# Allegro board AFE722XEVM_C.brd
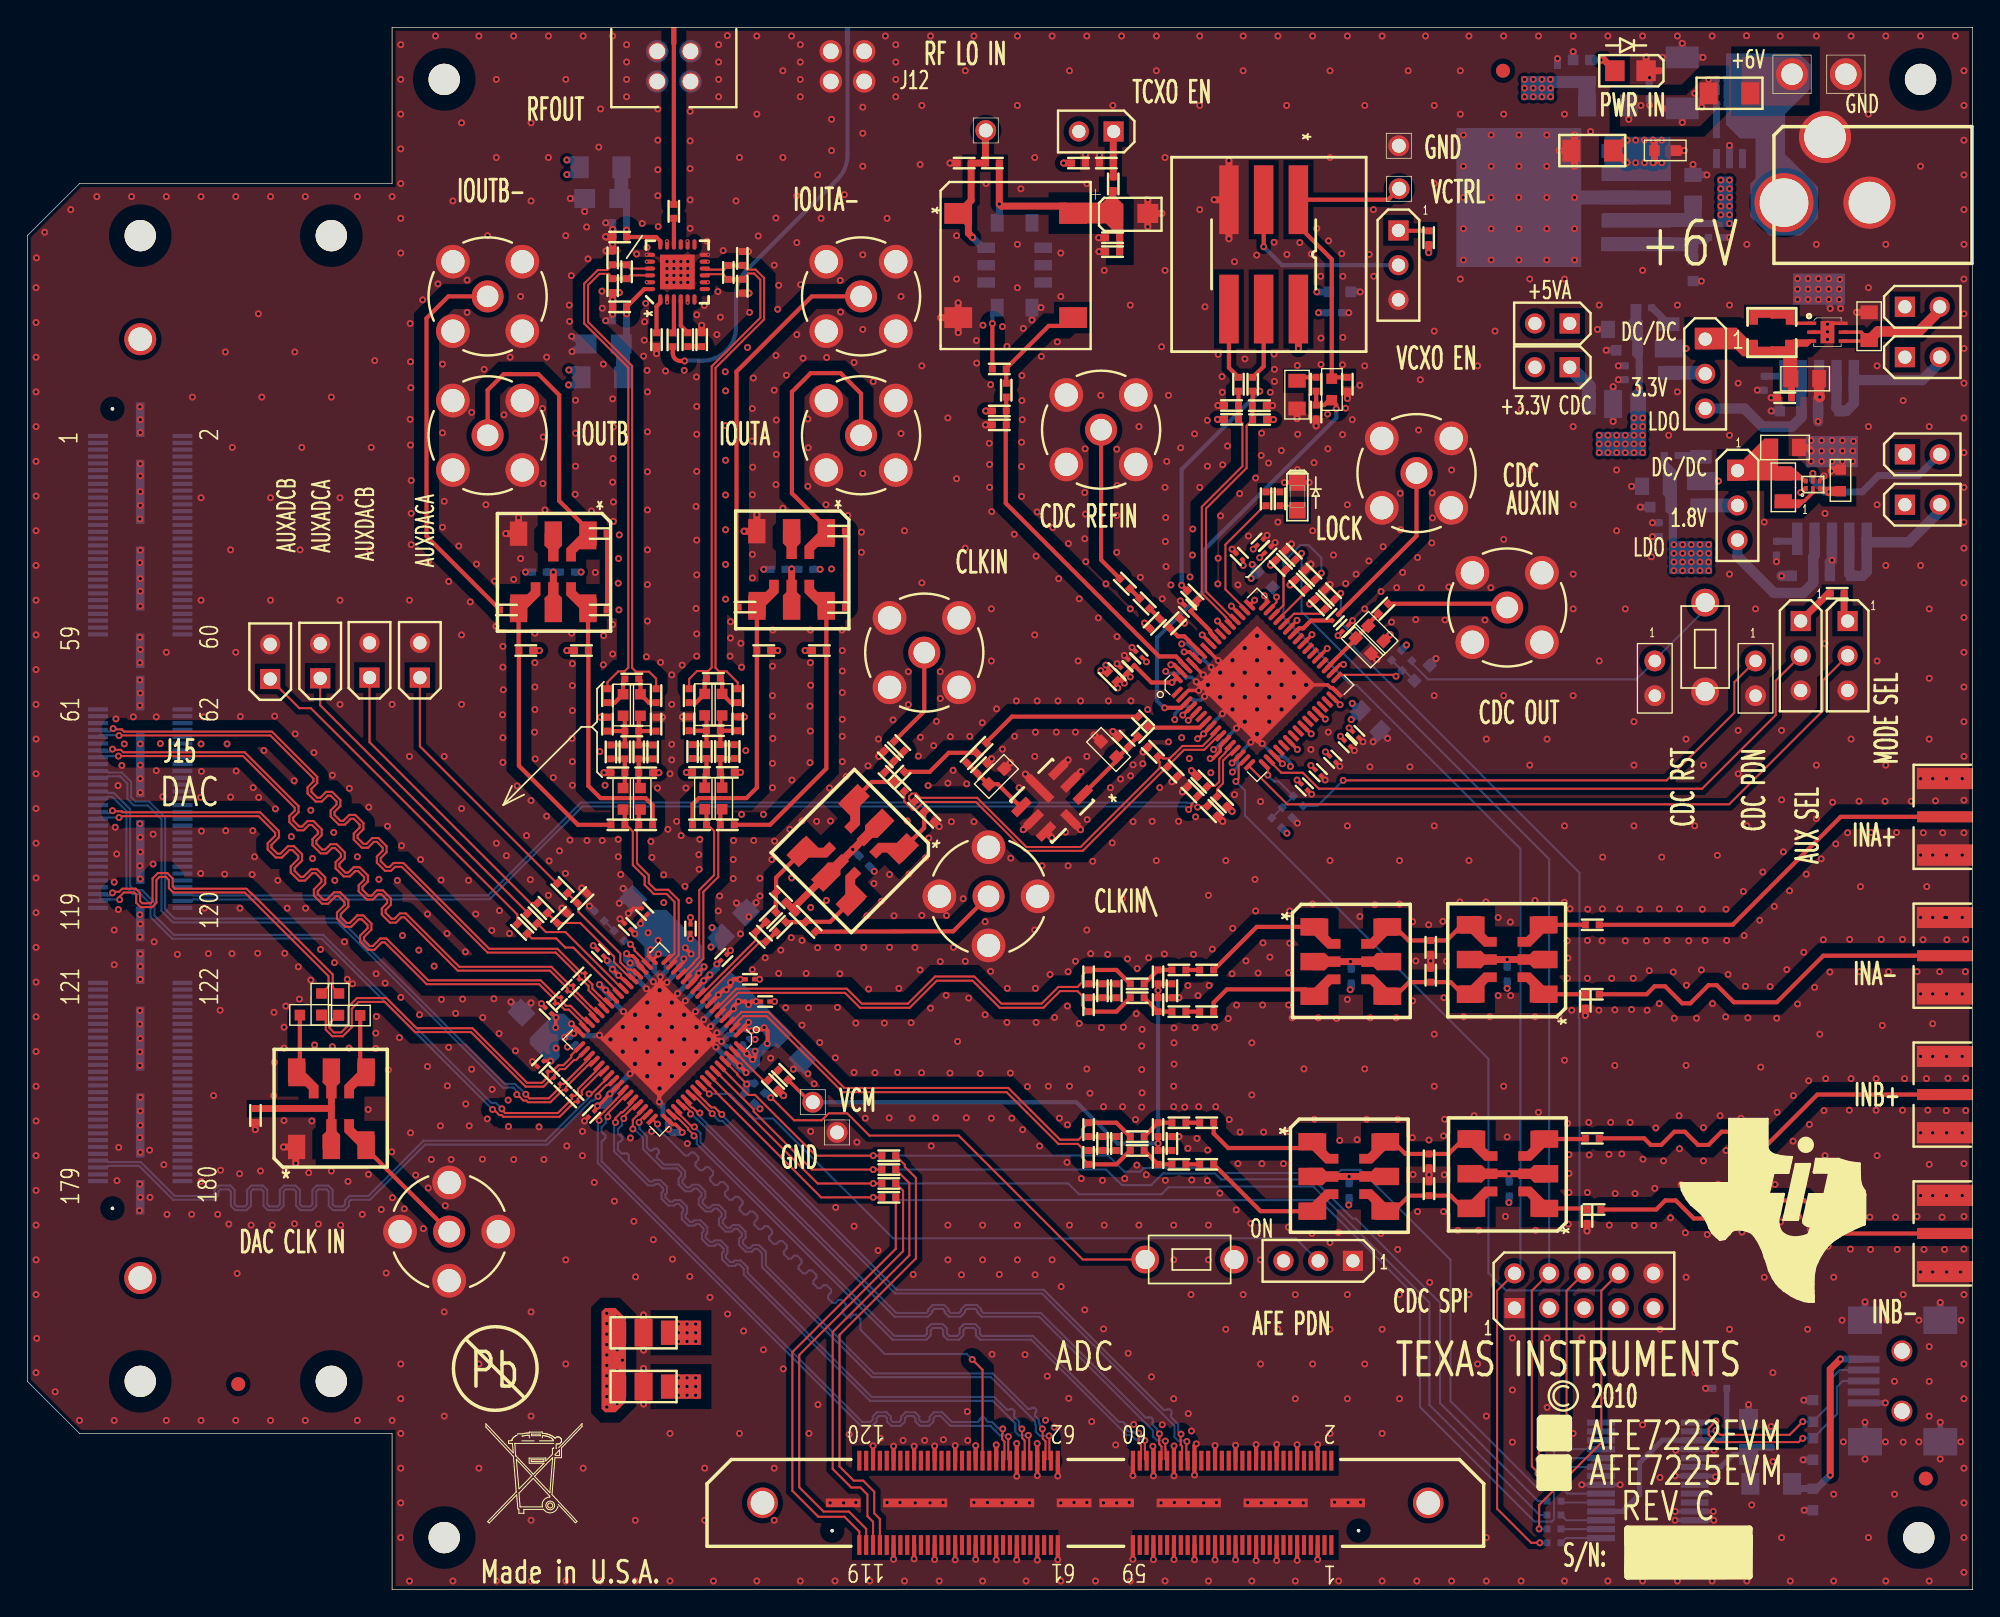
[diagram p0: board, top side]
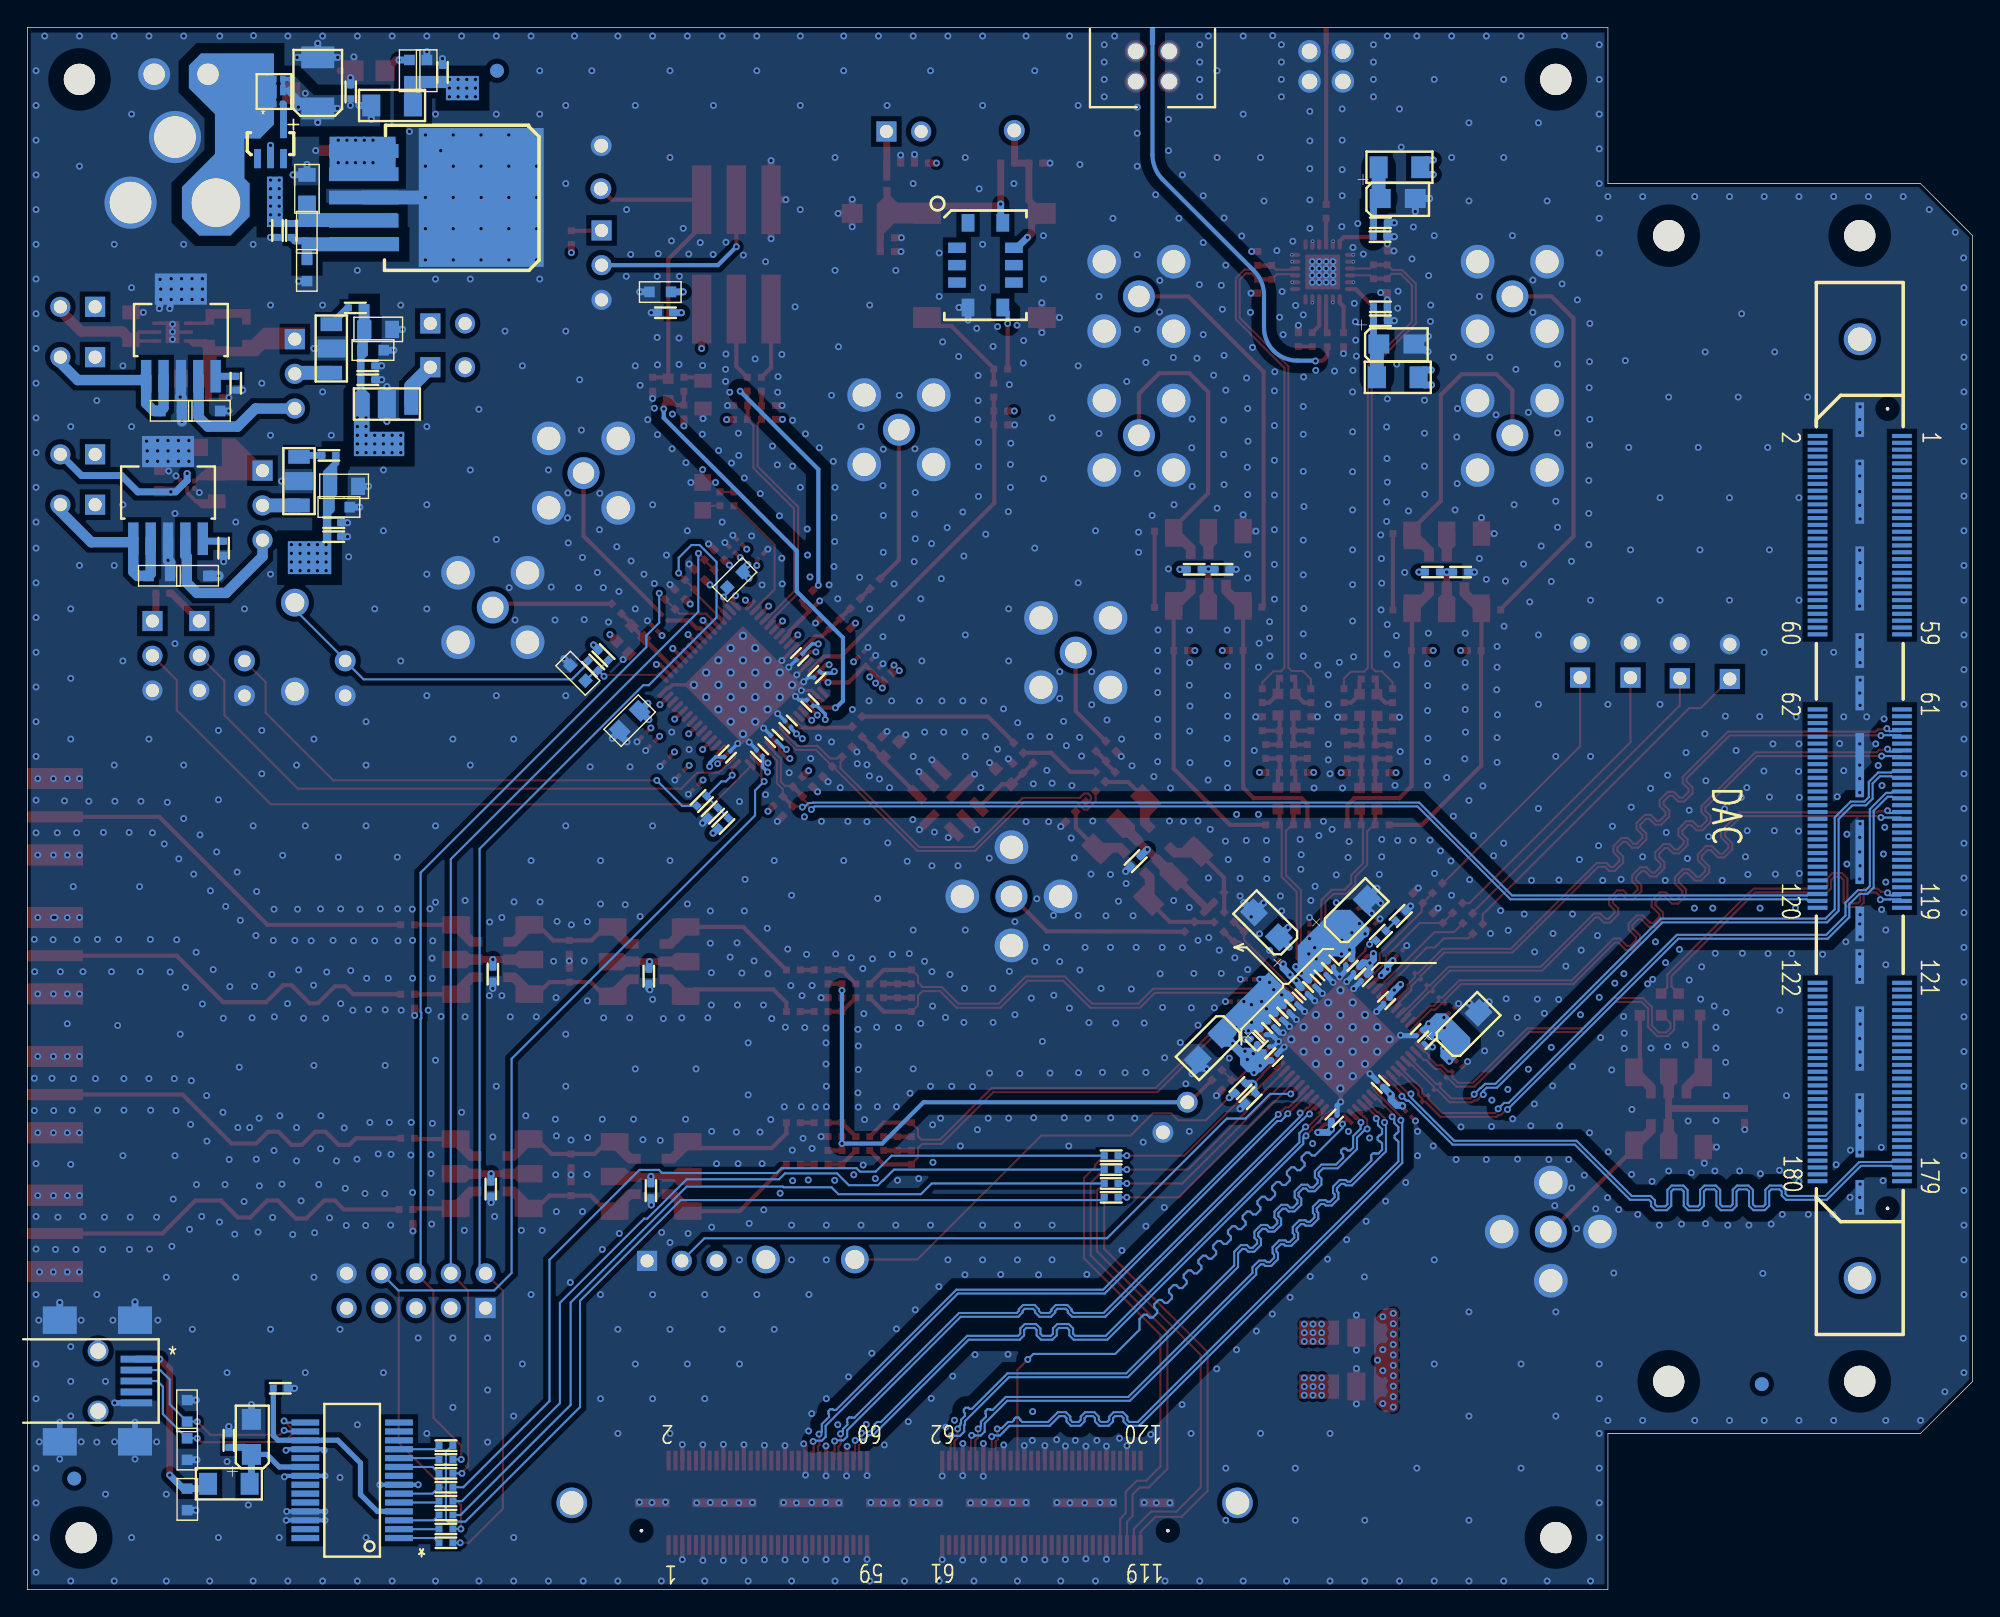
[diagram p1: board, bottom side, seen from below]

Outline 142.24 x 114.3 mm; copper layers: TOP, L2_GND, L3_PWR, L4_PWR, L5_GND, BOTTOM. Coordinates in mm from the lower left corner of the outline.
Outline path: 0,99.06 0,15.24 3.81,11.43 26.67,11.43 26.67,0 142.24,0 142.24,114.3 26.67,114.3 26.67,102.87 3.81,102.87 0,99.06

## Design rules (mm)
net group ADC_DCLKOUT: nets ADC_DCLKOUTN ADC_DCLKOUTP
net group ADC_FCLKOUT: nets ADC_FCLKOUTN ADC_FCLKOUTP
net group ADCA_DATA_0: nets ADCA_DATA_0N ADCA_DATA_0P
net group ADCA_DATA_1: nets ADCA_DATA_1N ADCA_DATA_1P
net group ADCB_DATA_0: nets ADCB_DATA_0N ADCB_DATA_0P
net group ADCB_DATA_1: nets ADCB_DATA_1N ADCB_DATA_1P
net group DAC_DCLK_IN: nets DAC_DCLK_INN DAC_DCLK_INP
net group DAC_FCLK_IN: nets DAC_FCLK_INN DAC_FCLK_INP
net group DACA_DATA_0: nets DACA_DATA_0N DACA_DATA_0P
net group DACA_DATA_1: nets DACA_DATA_1N DACA_DATA_1P
net group DACB_DATA_0: nets DACB_DATA_0N DACB_DATA_0P
net group DACB_DATA_1: nets DACB_DATA_1N DACB_DATA_1P
net group DP1: nets QN1 QP1
net group DP2: nets IN1 IP1
net group DP3: nets N31634141 N31634154
net group FPGA_CLK: nets FPGA_CLKN FPGA_CLKP
net group PWR: nets N29978744 N29978893
net group SYNCIN: nets SYNCINN SYNCINP
net group Y1: nets Y1N Y1P
net group 50 OHM: nets N27753768
net group PWR_PH: nets N27753749

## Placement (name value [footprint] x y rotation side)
C1  .1uF  [0402]  54.61 36.83 315 top
C2  .01uF  [0201]  50.93 46.25 45 top
C3  10uF  [TANT_A]  51.64 48.64 45 bottom
C4  4700pF  [0201]  48.87 43.82 225 bottom
C5  .01uF  [0201]  42.85 43.1 315 bottom
C6  4700pF  [0201]  37.54 38.46 225 top
C7  .01uF  [0201]  40.46 40.74 315 bottom
C8  4700pF  [0201]  38.1 42.37 135 top
C9  .01uF  [0201]  43.31 36.98 45 bottom
C10  4700pF  [0201]  41.25 34.8 225 top
C11  10uF  [TANT_A]  37.03 41.3 135 bottom
C12  .01uF  [0201]  44.5 44.78 315 bottom
C13  4700pF  [0201]  45.06 45.36 315 bottom
C14  .01uF  [0201]  45.14 49.63 135 top
C15  .01uF  [0201]  46.94 45.77 225 bottom
C16  .01uF  [0201]  48.31 44.37 225 bottom
C17  4700pF  [0201]  43.89 48.51 135 top
C18  10uF  [TANT_A]  45.21 49.63 135 bottom
C19  4700pF  [0201]  39.9 40.18 315 bottom
C20  .01uF  [0201]  46.69 34.49 135 bottom
C21  4700pF  [0201]  47.5 45.21 225 bottom
C22  4700pF  [0201]  48.49 48.36 90 top
C23  4700pF  [0201]  52.83 44.65 0 top
C24  4700pF  [0201]  50.75 41.94 225 bottom
C25  4700pF  [0201]  53.95 43.03 0 top
C26  4700pF  [0201]  51.87 40.82 225 bottom
C27  4700pF  [0201]  51.08 38.94 135 bottom
C28  .01uF  [0201]  51.64 39.52 135 bottom
C29  .01uF  [0201]  49.63 43.05 225 bottom
C30  .01uF  [0201]  52.53 40.11 45 bottom
C31  .01uF  [0201]  50.19 42.49 225 bottom
C32  .01uF  [0201]  51.31 41.38 225 bottom
C33  .01uF  [0201]  45.62 45.92 315 bottom
C34  4700pF  [0201]  41.91 46.58 135 top
C35  10uF  [TANT_A]  55.75 39.7 315 bottom
C36  .1uF  [0402]  84.07 34.16 180 top
C37  .1uF  [0402]  83.69 32.51 270 top
C38  3.3pF  [0402]  78.61 32.51 270 top
C39  .1uF  [0402]  108.36 29.44 90 bottom
C40  .1uF  [0402]  96.65 29.31 90 bottom
C41  .1uF  [0402]  84.07 31.11 180 top
C42  .1uF  [0402]  84.07 45.34 180 top
C43  .1uF  [0402]  83.69 43.94 90 top
C44  3.3pF  [0402]  78.61 43.69 270 top
C45  .1uF  [0402]  108.2 45.16 90 bottom
C46  .1uF  [0402]  96.8 45.01 90 bottom
C47  .1uF  [0402]  84.07 42.29 180 top
C48  .1uF  [0402]  96.52 88.32 90 top
C49  .1uF  [0402]  94.23 86.28 90 top
C50  .1uF  [0603]  95.96 94.95 0 bottom
C51  .1uF  [0402]  54.28 49.12 225 top
C52  22uF  [0805]  92.84 87.43 90 top
C53  100pF  [0402]  95.71 93.42 0 bottom
C54  0 ohm  [0402]  89.6 88.06 270 top
C55  .1uF  [0402]  55.02 48.39 225 top
C56  .1uF  [0402]  61.29 53.21 315 bottom
C57  10nF  [0402]  81.79 72.06 315 top
C58  0 ohm  [0402]  88.56 88.06 270 top
C59  .022uF  [0201]  91.06 61.14 135 bottom
C60  .1uF  [0402]  16.68 34.82 90 top
C61  .022uF  [0201]  80.72 67.84 315 top
C62  100pF  [0201]  97.13 62.56 315 top
C63  .022uF  [0201]  88.62 75.59 135 top
C64  .022uF  [0201]  85.78 68.25 315 bottom
C65  100pF  [0201]  80.16 67.26 315 top
C66  100pF  [0201]  90.14 76.63 45 top
C67  100pF  [0201]  81.28 68.43 135 top
C68  .022uF  [0201]  90.7 76.07 45 top
C69  100pF  [0201]  96.37 70.33 45 top
C70  22pF  [0402]  68.96 60.76 225 top
C71  22pF  [0402]  81.66 62.87 45 top
C72  1pF  [0402]  80.24 61.93 315 top
C73  1pF  [0402]  69.72 59.99 225 top
C74  .1uF  [0402]  99.06 71.68 225 top
C75  1uF  [0603]  101.98 67.06 45 bottom
C76  10nF  [0201]  84.51 66.95 315 bottom
C77  4.7uF  [0805]  98.2 63.58 315 bottom
C78  10nF  [0201]  85.01 64.87 45 bottom
C79  .1uF  [0402]  54.76 74.65 180 bottom
C80  10nF  [0201]  88.7 61.21 45 bottom
C81  .1uF  [0402]  37.31 74.45 180 bottom
C82  10nF  [0201]  87.66 62.28 45 bottom
C83  10nF  [0201]  95.63 71.12 45 top
C84  10nF  [0201]  86.61 63.32 45 bottom
C85  10nF  [0201]  84.84 71.81 315 top
C86  10nF  [0201]  93.37 58.72 315 top
C88  10nF  [0201]  96.52 61.9 315 top
C89  10nF  [0402]  92.2 56.77 315 bottom
C90  .01uF  [0402]  43.69 61.42 90 top
C91  4.7pF  [0402]  44.32 62.81 0 top
C92  4.7pF  [0402]  44.32 66.62 0 top
C94  .01uF  [0402]  44.7 61.42 90 top
C95  4.7pF  [0402]  42.8 95.53 90 top
C96  4.7pF  [0402]  42.8 97.31 270 top
C97  4.7uF  [TANT_A]  42.14 91.14 180 bottom
C98  1000pF  [0402]  43.18 93.85 180 bottom
C99  .1uF  [0402]  43.18 92.84 180 bottom
C100  3.3pF  [0402]  43.18 93.85 180 top
C101  3.3pF  [0402]  43.18 98.96 180 top
C102  1000pF  [0402]  43.21 98.98 180 bottom
C103  22pF  [0402]  47.19 91.57 90 top
C104  .1uF  [0402]  43.18 100 180 bottom
C105  4.7uF  [TANT_A]  42.04 101.78 180 bottom
C106  22pF  [0402]  47.27 100.97 90 top
C107  22pF  [0402]  48.29 91.32 270 top
C108  4.7pF  [0402]  52.28 95.49 90 top
C109  4.7pF  [0402]  52.28 97.27 270 top
C110  .01uF  [0402]  51.69 61.44 90 top
C111  4.7pF  [0402]  50.04 62.84 180 top
C112  4.7pF  [0402]  50.04 66.67 180 top
C114  .01uF  [0402]  48.64 61.44 90 top
C115  .1uF  [0402]  127.51 11.05 90 bottom
C116  10nF  [0603]  130.56 6.6 270 bottom
C117  4.7uF  [TANT_A]  125.86 11.18 90 bottom
C118  47pF  [0603]  130.56 10.29 270 bottom
C119  47pF  [0603]  130.56 13.08 90 bottom
C120  .1uF  [0402]  123.62 14.73 180 bottom
C121  47uF  [TANT_B]  121.01 110.24 90 bottom
C122  .1uF  [0402]  118.59 109.7 90 bottom
C123  1uF  [0603]  113.03 111.12 90 bottom
C124  .01uF  [0402]  111.89 111.12 90 bottom
C125  10uF  [1206]  114.43 105.28 180 top
C128  .1uF  [0402]  123.95 99.31 270 bottom
C130  10uF  [0805]  134.67 92.43 90 top
C131  10uF  [0805]  116.59 92.2 180 bottom
C132  10nF  [0402]  128.37 87.2 180 top
C133  10uF  [0805]  130 88.6 0 top
C135  10nF  [0402]  127 88.14 270 bottom
C136  1uF  [0603]  128.93 86.23 180 bottom
C137  2.2uF  [0603]  132.59 81.15 90 top
C138  4.7uF  [0805]  128.52 83.57 0 top
C139  .1uF  [0402]  119.71 78.05 180 bottom
C140  1uF  [0603]  132.59 74.17 180 bottom
C141  .01uF  [0402]  127.89 76.07 270 bottom
C142  4.7uF  [0603]  129.79 74.17 180 bottom
C143  1uF  [0603]  116.97 90.68 180 bottom
C144  10nF  [0201]  95.45 60.76 315 top
C145  .1uF  [0402]  117.22 89.53 180 bottom
C146  10nF  [0201]  94.39 59.77 315 top
C147  10nF  [0402]  117.22 88.52 180 bottom
C148  10uF  [0805]  119.08 80.72 180 bottom
C149  1uF  [0603]  119.46 79.2 180 bottom
C150  10nF  [0402]  119.71 77.04 180 bottom
C151  2.2uF  [0603]  131.72 86.23 180 bottom
C177  .1uF  [0402]  71.58 87.63 270 top
C178  100pF  [0402]  79.22 97.89 180 top
C179  4.7uF  [0402]  76.99 104.37 0 top
C180  .1uF  [0402]  78.77 104.37 180 top
C181  10uF  [TANT_A]  80.64 100.69 0 top
C182  .1uF  [0402]  79.22 98.91 180 top
C186  1uF  [0603]  119.76 105.28 0 top
C187  10uF  [0805]  121.79 102.49 90 bottom
C414  15pF  [0402]  122.94 99.31 270 bottom
D1  GREEN  [SMD_LED_0805]  92.86 79.98 90 top
D2  Blue  [LED_0805]  117.22 111.12 0 top
F3  2 AMP 63V FAST SMD  [1206]  124.46 109.47 180 top
FB4  68 ohm @ 100MHz  [1206]  42.04 88.7 0 bottom
FB5  68 ohm @ 100MHz  [1206]  41.91 104.06 0 bottom
FB6  68 OHM @ 100MHz  [1206]  127.51 7.75 0 bottom
FB7  68 ohm @ 100MHz  [1206]  115.57 108.59 0 bottom
FB9  27uF  [1206_BEAD_NFM31P]  120.02 90.81 90 bottom
FB11  27uF  [1206_BEAD_NFM31P]  45.06 14.86 180 top
FB12  27uF  [1206_BEAD_NFM31P]  122.38 81.1 90 bottom
FB13  1K  [IND_0402]  79.32 66.8 135 top
FB15  27uF  [1206_BEAD_NFM31P]  115.95 86.74 180 bottom
FB17  27uF  [1206_BEAD_NFM31P]  45.06 18.8 180 top
FB25  1K  [0402]  79.4 102.97 90 top
FLT1  245.76MHz  [FILTER_8_SM_150X150]  74.93 57.71 225 top
J1  SMA_END_JACK_RND  [SMA_SMEL_250X215]  142.24 36.22 270 top
J2  SMA_END_JACK_RND  [SMA_SMEL_250X215]  142.24 26.06 270 top
J3  SMA_END_JACK_RND  [SMA_SMEL_250X215]  142.24 56.54 270 top
J4  SMA_END_JACK_RND  [SMA_SMEL_250X215]  142.24 46.38 270 top
J5  SMA_PCB_THVT  [SMA_THVT_312X312]  60.96 84.45 0 top
J6  SMA_PCB_THVT  [SMA_THVT_312X312]  60.96 94.62 0 top
J7  SMA_PCB_THVT  [SMA_THVT_312X312]  33.66 84.45 0 top
J8  SMA_PCB_THVT  [SMA_THVT_312X312]  33.66 94.62 0 top
J9  SMA_PCB_THVT  [SMA_THVT_312X312]  78.51 84.86 270 top
J10  SMA_PCB_THVT  [SMA_THVT_312X312]  101.57 81.69 90 top
J11  SMA_PCB_THVT  [SMA_THVT_312X312]  108.2 71.86 270 top
J12  SMA_END_JACK_RND  [SMA_SMEL_218X247_096]  59.97 114.3 180 bottom
J13  SMA_END_JACK_RND  [SMA_SMEL_218X247_096]  47.27 114.3 0 top
J14  QTH-060-01-F-D-A-RT1  [CON_SMVT_120POS_QTH_SAMTEC_RT1]  78.11 6.35 180 top
J15  CON, SMVT, 180POS, HS GND PLANE, QTH  [CON_SMVT_180POS_QTH_SAMTEC_RT1]  6.22 86.36 270 bottom
J16  USB_MINI_AB  [CON_SMRT_USBMNE20_F]  137.72 15.27 180 bottom
J17  CONN JACK PWR  [CON_RAPC722_JACK_THVT_3]  131.57 101.47 90 top
J18  SMA_PCB_THVT  [SMA_THVT_312X312]  65.58 68.55 90 top
J19  SMA_PCB_THVT  [SMA_THVT_312X312]  70.28 50.72 225 top
J20  HMTSW-105-07-G-D-.240  [HDR_THVT_2X5_100_M]  108.74 20.6 90 top
J21  SMA_PCB_THVT  [SMA_THVT_312X312]  30.84 26.19 135 top
JP1  HEADER_1x3_100_430L  [HDR_THVT_1X3_100_M]  96.93 24.05 270 top
JP2  HEADER_1x2_100_430L  [HDR_THVT_1X2_100_M]  28.7 66.73 180 top
JP3  HEADER_1x2_100_430L  [HDR_THVT_1X2_100_M]  25.02 66.73 180 top
JP4  HEADER 3POS  [HDR_THVT_1X3_100_M]  100.25 99.44 0 top
JP5  HEADER 3POS  [HDR_THVT_1X3_100_M]  133.1 70.87 0 top
JP6  HEADER 2POS  [JUMPER2]  119 67.95 270 top
JP7  HEADER 3POS  [HDR_THVT_1X3_100_M]  129.67 70.87 0 top
JP8  HEADER 2POS  [JUMPER2]  126.37 67.95 270 top
JP10  HEADER_1x2_100_430L  [HDR_THVT_1X2_100_M]  112.78 92.63 270 top
JP11  HEADER_1x2_100_430L  [HDR_THVT_1X2_100_M]  137.29 93.85 90 top
JP12  HEADER 3POS  [HDR_THVT_1X3_100_M]  122.68 91.49 0 top
JP13  JUMPER_1x3_100_430L  [HDR_THVT_1X3_100_M]  125.04 81.86 0 top
JP14  HEADER_1x2_100_430L  [HDR_THVT_1X2_100_M]  137.29 79.38 90 top
JP15  HEADER_1x2_100_430L  [HDR_THVT_1X2_100_M]  21.41 66.67 180 top
JP16  HEADER_1x2_100_430L  [HDR_THVT_1X2_100_M]  17.75 66.62 180 top
JP17  HEADER_1x2_100_430L  [HDR_THVT_1X2_100_M]  79.43 106.68 270 top
JP18  HEADER_1x2_100_430L  [HDR_THVT_1X2_100_M]  112.78 89.43 270 top
JP19  HEADER_1x2_100_430L  [HDR_THVT_1X2_100_M]  137.29 90.17 90 top
JP20  HEADER_1x2_100_430L  [HDR_THVT_1X2_100_M]  137.29 83.06 90 top
L1  72nH  [0402]  79.63 32.51 270 top
L2  72nH  [0402]  79.63 43.69 270 top
L8  180nH  [0603]  70.87 59.49 45 top
L9  180nH  [0603]  79.07 61.48 135 top
L10  180nH  [0603]  43.56 64.72 270 top
L12  180nH  [0603]  44.83 64.72 270 top
L14  180nH  [0603]  50.8 64.74 270 top
L16  180nH  [0603]  49.53 64.74 270 top
L18  2.2uH  [LPS3015]  127.56 91.97 270 top
L19  2.2uH  [0805]  128.4 80.64 90 top
NOREF  -  []  0 15.24 90 top
NOREF#2  -  [unnamed#2]  30.48 3.81 0 top
NOREF#3  -  [unnamed#2]  8.25 15.24 0 top
NOREF#4  -  []  26.67 102.87 90 top
NOREF#5  -  []  -18.92 115.57 0 top
NOREF#6  -  []  40.51 52.96 0 top
NOREF#7  -  [unnamed#2]  138.3 3.81 0 top
NOREF#8  -  []  110.06 11.53 0 top
NOREF#9  -  []  36.98 8.66 0 top
NOREF#10  -  []  142.24 0 90 top
NOREF#11  -  []  -12.24 58.65 0 top
NOREF#12  -  []  26.67 114.3 0 top
NOREF#13  -  [unnamed#2]  22.23 99.06 0 top
NOREF#14  -  [unnamed#2]  30.48 110.49 0 top
NOREF#15  -  []  698.75 109.09 0 top
NOREF#16  -  []  -130.81 -80.01 0 top
NOREF#17  -  []  -123.19 -184.15 0 top
NOREF#18  -  [unnamed#2]  138.43 110.49 0 top
NOREF#19  -  [unnamed#3]  138.81 8.13 0 top
NOREF#20  -  [unnamed#3]  107.9 111.12 0 top
NOREF#21  -  []  32.99 0.56 0 top
NOREF#22  -  [unnamed#2]  8.25 99.06 0 top
NOREF#23  -  [unnamed#2]  22.23 15.24 0 top
NOREF#24  -  []  68.29 52.49 0 top
NOREF#25  -  [unnamed#3]  15.42 15.04 0 top
NOREF#26  -  [unnamed#3]  138.81 8.13 180 bottom
NOREF#27  -  [unnamed#3]  107.9 111.12 180 bottom
NOREF#28  -  [unnamed#3]  15.42 15.04 180 bottom
Q1  CSD17313Q2  [MOSFET_8_2MMX2MM_0P65]  124.21 109.6 180 bottom
R1  0 ohm  [0402]  63.12 30.73 0 bottom
R2  10  [0402]  53.44 36.78 135 bottom
R3  0 ohm  [0402]  63.12 30.73 0 top
R5  10K  [0402]  52.88 35.86 315 bottom
R6  0 ohm  [0402]  63.12 29.72 0 bottom
R7  10  [0402]  55.17 37.74 135 top
R8  0 ohm  [0402]  63.12 29.72 0 top
R9  0 ohm  [0402]  63.12 28.7 0 bottom
R10  0 ohm  [0402]  63.12 28.7 0 top
R11  0 ohm  [0402]  63.12 31.75 0 bottom
R12  100  [0402]  58.04 68.71 0 top
R13  100  [0402]  53.72 68.71 180 top
R14  6.98  [0402]  41.91 49.2 315 bottom
R15  953  [0402]  43.36 47.75 315 bottom
R16  0  [0402]  39.04 51.41 135 top
R17  0  [0402]  37.57 49.96 135 top
R18  0  [0402]  36.83 49.2 135 top
R19  0  [0402]  36.09 48.44 135 top
R20  0  [0402]  86.36 34.16 0 top
R21  10  [0402]  81.03 33.15 180 top
R22  0  [0402]  114.3 33.02 180 top
R23  10  [0402]  77.6 33.53 270 top
R24  49.9  [0402]  102.49 31.24 270 top
R25  24.9  [0402]  82.68 33.53 270 top
R26  49.9  [0402]  102.49 29.21 270 top
R27  24.9  [0402]  82.68 31.5 270 top
R28  10  [0402]  77.6 31.5 270 top
R29  0  [0402]  114.68 27.81 0 top
R30  0  [0402]  86.36 31.11 0 top
R31  0  [0402]  114.05 27.18 270 top
R32  10  [0402]  81.03 32.13 180 top
R33  0  [0402]  86.36 45.34 0 top
R34  10  [0402]  81.03 44.32 180 top
R35  10  [0402]  77.6 44.7 270 top
R36  0  [0402]  114.3 48.64 180 top
R37  49.9  [0402]  102.62 46.86 270 top
R38  24.9  [0402]  82.68 44.7 270 top
R39  49.9  [0402]  102.62 44.83 270 top
R40  24.9  [0402]  82.68 42.67 270 top
R41  10  [0402]  77.6 42.67 270 top
R42  0  [0402]  114.55 43.56 0 top
R43  0  [0402]  86.36 42.29 0 top
R44  10  [0402]  81.03 43.31 180 top
R45  0  [0402]  113.92 42.93 270 top
R46  0  [0402]  51.05 55.96 180 top
R47  0  [0402]  59.44 71.86 0 top
R48  0  [0402]  57.05 74.65 0 bottom
R49  0  [0402]  59.18 77.44 180 top
R50  0  [0402]  39.62 74.45 0 bottom
R51  0 ohm  [0402]  63.12 31.75 0 top
R52  49.9  [0402]  40.67 50.67 45 top
R53  100  [0402]  40.64 68.71 0 top
R54  100  [0402]  36.32 68.71 180 top
R55  100  [0201]  40.03 35.92 315 top
R56  0  [0402]  49.28 55.96 0 top
R57  0  [0402]  52.35 71.88 180 top
R58  0  [0402]  45.09 55.96 180 top
R59  0  [0402]  42.01 71.68 0 top
R60  100  [0201]  39.17 36.78 315 top
R61  0  [0402]  41.76 77.27 180 top
R62  100  [0201]  38.28 37.67 315 top
R63  49.9  [0402]  39.19 49.23 45 top
R64  0  [0603]  22.78 42.83 90 top
R65  100  [0201]  38.81 43.1 225 top
R66  100  [0201]  39.7 43.99 225 top
R67  100  [0201]  40.56 44.88 225 top
R68  0  [0402]  43.31 55.96 0 top
R69  0  [0402]  34.9 71.68 180 top
R70  1K  [0603]  95.38 87.81 270 top
R71  7.15K  [0402]  94.23 88.06 270 top
R72  0 ohm  [0402]  81.66 63.42 315 top
R73  10K  [0402]  102.46 98.78 270 top
R74  0 ohm  [0402]  62.97 59.54 135 top
R75  0 ohm  [0402]  80.16 73.69 135 top
R76  0 ohm  [0402]  63.86 59.56 45 top
R77  49.9  [0402]  62.92 61.06 135 top
R78  100  [0402]  55.19 50.57 315 top
R79  0 ohm  [0402]  63.86 58.67 315 top
R80  130  [0402]  90.23 85.6 0 top
R81  0 ohm  [0402]  65.13 57.38 135 top
R82  100  [0402]  56.64 49.12 315 top
R83  82.5  [0402]  90.21 86.63 0 top
R84  49.9  [0402]  85.09 72.82 135 top
R85  10K  [0402]  82.35 70.59 225 top
R86  0 ohm  [0402]  66.04 56.46 315 top
R87  130  [0402]  87.92 85.62 180 top
R88  100  [0402]  53.72 47.68 315 top
R89  82.5  [0402]  87.92 86.63 180 top
R90  10K  [0402]  83.81 70.61 225 top
R91  0 ohm  [0402]  90.58 79.68 270 top
R92  750  [0402]  91.59 79.93 90 top
R93  0  [0603]  21.51 42.83 90 top
R94  0  [0603]  23.55 42.02 180 top
R95  0  [0603]  20.71 42.04 0 top
R96  150  [0402]  82.21 61.39 135 top
R97  150  [0402]  83.83 59.77 315 top
R98  10K  [0402]  94.44 72.18 135 top
R99  10K  [0402]  93 73.62 135 top
R100  10K  [0402]  91.56 75.06 135 top
R101  10K  [0603]  90.5 73.89 135 bottom
R102  10K  [0402]  95.33 72.72 315 top
R103  10K  [0402]  93.9 74.16 315 top
R104  10K  [0402]  92.46 75.62 315 top
R105  ??  [0603]  98.6 69.95 315 top
R106  10K  [0402]  100.2 68.45 45 bottom
R107  10K  [0402]  132.21 72.9 180 top
R108  ??  [0603]  97.68 69.06 135 top
R109  100  [0402]  100.97 67.69 45 bottom
R110  10K  [0402]  91.44 56.01 315 bottom
R111  100  [0402]  92.84 57.79 135 bottom
R112  0 ohm  [0402]  63.65 61.8 135 top
R113  115  [0402]  43.31 59.77 0 top
R114  0  [0603]  43.56 57.86 270 top
R115  0  [0402]  42.67 61.42 90 top
R116  634  [0402]  42.42 63.45 90 top
R117  37.4  [0402]  42.42 65.28 270 top
R118  115  [0402]  45.09 59.77 180 top
R119  1.5K  [0603]  121.79 96.52 90 bottom
R120  0  [0603]  44.83 57.86 270 top
R121  0  [0402]  45.72 61.42 90 top
R122  634  [0402]  45.97 63.45 90 top
R123  0  [0402]  46 91.58 90 top
R124  49.9  [0402]  49.31 91.58 90 top
R125  37.4  [0402]  45.97 65.28 270 top
R126  115  [0402]  51.05 59.79 180 top
R127  0  [0603]  50.8 57.89 270 top
R128  0  [0402]  50.67 61.44 90 top
R129  634  [0402]  51.94 63.47 90 top
R130  37.4  [0402]  51.94 65.28 270 top
R131  4.7K  [0603]  121.79 99.31 90 bottom
R132  115  [0402]  49.28 59.79 0 top
R133  0  [0603]  49.53 57.89 270 top
R134  0  [0402]  49.66 61.44 90 top
R135  634  [0402]  48.39 63.47 90 top
R136  0  [0402]  111.76 3.43 0 bottom
R137  0  [0402]  111.76 6.48 0 bottom
R138  0  [0402]  111.76 5.46 0 bottom
R139  0  [0402]  111.76 10.54 0 bottom
R140  37.4  [0402]  48.39 65.28 270 top
R141  0  [0402]  111.76 7.49 0 bottom
R142  10K  [0603]  114.3 111.12 270 bottom
R143  0  [0402]  118.14 93.78 180 bottom
R144  0 ohm  [0402]  69.67 61.49 225 top
R145  0  [0402]  120.07 82.98 180 bottom
R148  130  [0402]  87.27 57.77 135 top
R149  130  [0402]  86.01 59.03 315 top
R150  82.5  [0402]  86.73 56.87 315 top
R151  82.5  [0402]  85.11 58.49 135 top
R154  130  [0402]  51.26 96.24 270 top
R155  130  [0402]  43.81 96.29 270 top
R157  0  [0402]  70.94 89.31 180 top
R158  0  [0402]  111.76 4.45 0 bottom
R159  0  [0402]  111.76 8.51 0 bottom
R160  0  [0402]  111.76 9.53 0 bottom
R161  0 ohm  [0402]  57.18 48.59 135 top
R164  10K  [0402]  68.63 104.37 0 top
R165  10K  [0402]  70.69 104.37 0 top
R166  10K  [0402]  71.2 86.23 0 top
R167  10K  [0402]  71.2 85.22 0 top
SW1  SW PUSHBUTTON  [SW_RESET_PTS635]  84.99 24.16 0 top
SW2  RESET  [SW_RESET_PTS635]  122.68 68.96 270 top
T1  ADTT1-1+  [TFMR_6_RF_DUAL_FOOTPRINT]  108.25 30.43 90 top
T2  ADTT1-1+  [TFMR_6_RF_DUAL_FOOTPRINT]  96.63 30.23 270 top
T3  ADTT1-1+  [TFMR_6_RF_DUAL_FOOTPRINT]  108.2 46.1 90 top
T4  ADTT1-1+  [TFMR_6_RF_DUAL_FOOTPRINT]  96.77 45.95 270 top
T5  ADT4-1WT  [TFMR_6_RF_DUAL_FOOTPRINT]  55.88 74.64 180 top
T6  ADTT1-1+  [TFMR_6_RF_DUAL_FOOTPRINT]  22.23 35.18 0 top
T7  ADT4-1WT  [TFMR_6_RF_DUAL_FOOTPRINT]  38.46 74.47 180 top
T9  ADT4-1WT  [TFMR_6_RF_DUAL_FOOTPRINT]  60.35 54.1 135 top
TP1  Test Point White  [TESTPOINT]  57.43 35.66 0 top
TP2  Test Point Black  [TESTPOINT]  59.21 33.45 0 top
TP3  Test Point Black  [TESTPOINT]  100.28 105.64 0 top
TP4  Test Point White  [TESTPOINT]  100.3 102.49 0 top
TP11  Testloop_Red  [TESTPOINT_62DIA]  129.03 110.87 0 top
TP12  Testloop_Black  [TESTPOINT_62DIA]  132.97 110.87 0 top
TP14  Testloop_White  [TESTPOINT]  70.08 106.76 0 top
U1  AFE7222 or AFE7225  [QFN64]  46.23 40.26 225 top
U2  CDCE72010  [QFN64]  89.91 66.2 45 top
U3  TRF370333  [QFN_24_163X163_0P50MM_PWRPAD]  47.53 96.4 90 top
U4  FT245RL  [SSOP_28_413X221_26]  118.49 8 0 bottom
U6  TPS62291  [SON_DRV_6]  131.62 92 0 top
U7  TPS79633  [SOT_223_6_TG]  130.38 92.15 180 bottom
U8  TPS62231  [SON_DRY_6]  130.56 80.9 0 top
U9  TPS79518  [SOT_223_6_TG]  131.32 80.26 180 bottom
U14  TPS7A4501KTT  [TO_263_6]  110.46 101.85 270 bottom
U16  TCXO 19.2MHz  [SMD_XTAL_7X5MM_D75ASERIES]  72.19 96.9 180 bottom
U17  TCXO 19.2MHz  [OSC_4_SM_460X386]  72.26 96.88 270 top
U18  TPS2400  [DBV5]  124.46 105.79 90 bottom
VCXO1  737.28MHZ  [VCXO_6_CUSTOM2]  90.4 97.69 270 top

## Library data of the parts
C1 C36 C37 C39-C43 C45-C50 C57 C60 C61 C89 C122 C125 C128 C139 C145 = CAP NP: tolerance: 10%
C2 C20 = CAP0402: tolerance: -20%/+80%
C3 C11 C18 C35 = CAP POL-B_10uF_10V
C4 C6 C13 C19 C21 C23-C27 C34 C75 C123 C136 C143 C149 C179 C186 = CAP NP_0: tolerance: 20%
C5 C7 C9 C12 C14-C16 C28-C33 = CAP NP_0: tolerance: -20%/+80%
C8 C10 C17 C22 = CAP0402: tolerance: 20%
C38 C44 = CAP0603: tolerance: +/-.25pF
C51 C55 = CAP0402: tolerance: 10%
C52 = CAP NP: tolerance: 20%
C53 C54 C58 C65 = CAP NP: tolerance: 5%
C56 = CAP0603: tolerance: 10%
C59 C63 C64 C68 C74 C77 C79 C81 C90 C94 C98 C99 C102 C104 C110 C114 C115 C120 C124 C177 C178 C180 C182 = CAP NP_0: tolerance: 10%
C62 C66 C67 C69 C95 C96 C103 C106-C109 C414 = CAP NP_0: tolerance: 5%
C70 C71 = CAP NP: tolerance: 2%
C72 C73 = CAP NP: tolerance: .25pF
C76 C78 C80 C82-C86 C88 C144 C146 = CAP NP: tolerance: 10V
C91 C92 C111 C112 = CAP NP_0: tolerance: .25pF
C97 C105 C117 = CAP POL-B_10uF_10V: tolerance: 10%
C100 C101 = CAP0402
C116 C118 C119 = CAP0603
C121 = CAP POL: tolerance: 20%
C130 C133 C137 C138 C141 C142 C151 C187 = CAP0201: tolerance: 10%
C131 C140 C148 = CAP0201: tolerance: 20%
C132 C135 C147 C150 = CAPACITOR_NP_4: tolerance: 10%
C181 = CAP POL-B_10uF_10V: tolerance: 20%
D1 D2 = LED
F3 = FUSE/SM
FB4-FB7 FB25 = FERRITE_BEAD
FB9 FB11 FB12 FB15 FB17 = BEAD_NFM31P
FB13 = FERRITE_BEAD_0402_H
FLT1 = TS-38S_0
J1-J4 J9-J11 J18 J19 = SMA-END_JACK_142-0711-821_ROUND
J5-J8 J21 = SMA_PCB_THVT_142-0701-201_REC
J12 J13 = SMA-END_JACK_142-0761-801_ROUND
J14 = CON_SMVT_120POS_QTH_SAMTEC
J15 = CON_SMVT_180POS_QTH_SAMTEC
J16 = USB_MINI_AB_MNE20-5G5P10
J17 = CONN JACK PWR
J20 = HEADER_2x5_100
JP1 JP12 = JUMPER_1x3_100
JP2 JP3 JP10 JP11 JP14-JP20 = JUMPER_1x2_100
JP4 = HEADER_1x3_0
JP5 JP7 = Jumper_1x3_smt
JP6 JP8 = HEADER_1x2_0: User Part Number: ***
JP13 = Jumper_1x3_100_1
L1 L2 = CHOKE_0
L8 L9 = INDUCTOR: tolerance: 5%
L10 L12 L14 L16 = IND0603_0: tolerance: 2%
L18 = IND1206
L19 = IND1206: tolerance: 20%
Q1 = PWR_MOSFET_CSD17313Q2
R1 R3 R6 R8-R11 R16-R20 R22 R29-R31 R33 R36 R42 R43 R45-R51 R56-R59 R61 R64 R68 R69 R72 R74-R76 R79 R81 R86 R91 R93-R95 R112 R114 R120 R123 R127 R133 R136-R139 R141 R143-R145 R157-R161 = R: tolerance: 5%
R2 R5 R12 R13 R53 R54 R71 R73 R85 R90 R98-R108 R110 R117 R124 R125 R130 R140 R164-R167 = R: tolerance: 1%
R7 R21 R23-R28 R32 R34 R35 R37-R41 R44 R52 R55 R60 R62 R63 R65-R67 R77 R78 R82 R88 R142 R154 R155 = RES0603: tolerance: 1%
R14 R15 = R_0: tolerance: 1%
R70 = RES0603
R80 R83 R87 R89 R92 R96 R97 R109 R111 R148-R151 = RESISTOR: tolerance: 1%
R84 = RES0402: tolerance: 1%
R113 R116 R118 R122 R126 R129 R132 R135 = R_5: tolerance: 1%
R115 R121 R128 R134 = R_5: tolerance: 5%
R119 R131 = R_4: tolerance: 1%
SW1 = SW PUSHBUTTON_1
SW2 = SPST_PB_KT11P3JM_0
T1-T4 T6 = XFMR_6_ADT4-1WT_2
T5 T7 = ADT4-1T_0
T9 = XFMR_6_ADT4-1WT
TP1-TP4 = T POINT R
TP11 TP12 TP14 = TESTLOOP_BLACK
U1 = AFE7225_2
U2 = ARES
U3 = HMC497LP4_2
U4 = FT245RL_0
U6 = TPS79633DCQ_3
U7 U9 = TPS79633DCQ_1
U8 = TPS79633DCQ_2
U14 = TPS79501DCQ_0
U16 = OSC-VECTRON_2
U17 = OSC-VECTRON_0
U18 = TPS2400
VCXO1 = VCXO_6

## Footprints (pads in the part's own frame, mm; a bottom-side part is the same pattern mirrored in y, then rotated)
0201
  rect 0.305x0.305 smd: 1(-0.305,0) 2(0.305,0)
0402
  rect 0.508x0.508 smd: 1(-0.635,0) 2(0.381,0)
0603
  rect 0.762x0.787 smd: 1(-0.787,0) 2(0.787,0)
0805
  rect 1.016x1.27 smd: 1(-1.016,0) 2(1.016,0)
1206
  rect 1.321x1.6 smd: 1(-1.524,0) 2(1.524,0)
1206_BEAD_NFM31P
  rect 1.016x1.575 smd: 1(-1.778,0) 3(1.778,0)
  rect 1.321x2.032 smd: 2(0,0)
CON_RAPC722_JACK_THVT_3
  round 4.318 hole 3.556: 1(0,3.124)
  round 3.81 hole 3.048: 2(0,-3.124) 3(4.801,0.127)
CON_SMRT_USBMNE20_F
  round 1.524 hole 1.143 unplated: (0.65,-2.2) (0.65,2.2)
  rect 2.311x0.508 smd: 1(3.45,1.6) 2(3.45,0.8) 3(3.45,0) 4(3.45,-0.8) 5(3.45,-1.6)
  rect 2.489x2.007 smd: 6(-2.15,-4.45) 7(3.35,-4.45) 8(3.35,4.45) 9(-2.15,4.45)
CON_SMVT_120POS_QTH_SAMTEC_RT1
  round 2.235 hole 1.727: (-24.329,0) (24.35,0)
  round 0.254 hole 1.016 unplated: (-19.233,2.032) (19.258,2.032)
  rect 0.305x1.448 smd: 1(-17.244,3.086) 2(-17.244,-3.086) 3(-16.744,3.086) 4(-16.744,-3.086) 5(-16.243,3.086) 6(-16.243,-3.086) 7(-15.743,3.086) 8(-15.743,-3.086) 9(-15.243,3.086) 10(-15.243,-3.086) 11(-14.742,3.086) 12(-14.742,-3.086) 13(-14.242,3.086) 14(-14.242,-3.086) 15(-13.741,3.086) 16(-13.741,-3.086) 17(-13.241,3.086) 18(-13.241,-3.086) 19(-12.741,3.086) 20(-12.741,-3.086) 21(-12.24,3.086) 22(-12.24,-3.086) 23(-11.74,3.086) 24(-11.74,-3.086) 25(-11.239,3.086) 26(-11.239,-3.086) 27(-10.739,3.086) 28(-10.739,-3.086) 29(-10.239,3.086) 30(-10.239,-3.086) 31(-9.738,3.086) 32(-9.738,-3.086) 33(-9.238,3.086) 34(-9.238,-3.086) 35(-8.738,3.086) 36(-8.738,-3.086) 37(-8.237,3.086) 38(-8.237,-3.086) 39(-7.737,3.086) 40(-7.737,-3.086) 41(-7.236,3.086) 42(-7.236,-3.086) 43(-6.736,3.086) 44(-6.736,-3.086) 45(-6.236,3.086) 46(-6.236,-3.086) 47(-5.735,3.086) 48(-5.735,-3.086) 49(-5.235,3.086) 50(-5.235,-3.086) 51(-4.735,3.086) 52(-4.735,-3.086) 53(-4.234,3.086) 54(-4.234,-3.086) 55(-3.734,3.086) 56(-3.734,-3.086) 57(-3.233,3.086) 58(-3.233,-3.086) 59(-2.733,3.086) 60(-2.733,-3.086) 61(2.758,3.086) 62(2.758,-3.086) 63(3.259,3.086) 64(3.259,-3.086) 65(3.759,3.086) 66(3.759,-3.086) 67(4.26,3.086) 68(4.26,-3.086) 69(4.76,3.086) 70(4.76,-3.086) 71(5.26,3.086) 72(5.26,-3.086) 73(5.761,3.086) 74(5.761,-3.086) 75(6.261,3.086) 76(6.261,-3.086) 77(6.761,3.086) 78(6.761,-3.086) 79(7.262,3.086) 80(7.262,-3.086) 81(7.762,3.086) 82(7.762,-3.086) 83(8.263,3.086) 84(8.263,-3.086) 85(8.763,3.086) 86(8.763,-3.086) 87(9.263,3.086) 88(9.263,-3.086) 89(9.764,3.086) 90(9.764,-3.086) 91(10.264,3.086) 92(10.264,-3.086) 93(10.765,3.086) 94(10.765,-3.086) 95(11.265,3.086) 96(11.265,-3.086) 97(11.765,3.086) 98(11.765,-3.086) 99(12.266,3.086) 100(12.266,-3.086) 101(12.766,3.086) 102(12.766,-3.086) 103(13.266,3.086) 104(13.266,-3.086) 105(13.767,3.086) 106(13.767,-3.086) 107(14.267,3.086) 108(14.267,-3.086) 109(14.768,3.086) 110(14.768,-3.086) 111(15.268,3.086) 112(15.268,-3.086) 113(15.768,3.086) 114(15.768,-3.086) 115(16.269,3.086) 116(16.269,-3.086) 117(16.769,3.086) 118(16.769,-3.086) 119(17.269,3.086) 120(17.269,-3.086)
  rect 2.54x0.635 smd: 121(-18.438,0) 124(-1.547,0) 125(1.565,0) 128(18.456,0)
  rect 4.699x0.635 smd: 122(-13.167,0) 123(-6.817,0) 126(6.835,0) 127(13.185,0)
CON_SMVT_180POS_QTH_SAMTEC_RT1
  round 2.337 hole 1.727: (-5.123,-2.032) (63.558,-2.032)
  round 0.254 hole 1.016 unplated: (-0.03,0) (58.466,0)
  rect 0.305x1.448 smd: 1(1.958,1.054) 2(1.958,-5.118) 3(2.459,1.054) 4(2.459,-5.118) 5(2.959,1.054) 6(2.959,-5.118) 7(3.459,1.054) 8(3.459,-5.118) 9(3.96,1.054) 10(3.96,-5.118) 11(4.46,1.054) 12(4.46,-5.118) 13(4.961,1.054) 14(4.961,-5.118) 15(5.461,1.054) 16(5.461,-5.118) 17(5.961,1.054) 18(5.961,-5.118) 19(6.462,1.054) 20(6.462,-5.118) 21(6.962,1.054) 22(6.962,-5.118) 23(7.463,1.054) 24(7.463,-5.118) 25(7.963,1.054) 26(7.963,-5.118) 27(8.463,1.054) 28(8.463,-5.118) 29(8.964,1.054) 30(8.964,-5.118) 31(9.464,1.054) 32(9.464,-5.118) 33(9.964,1.054) 34(9.964,-5.118) 35(10.465,1.054) 36(10.465,-5.118) 37(10.965,1.054) 38(10.965,-5.118) 39(11.466,1.054) 40(11.466,-5.118) 41(11.966,1.054) 42(11.966,-5.118) 43(12.466,1.054) 44(12.466,-5.118) 45(12.967,1.054) 46(12.967,-5.118) 47(13.467,1.054) 48(13.467,-5.118) 49(13.967,1.054) 50(13.967,-5.118) 51(14.468,1.054) 52(14.468,-5.118) 53(14.968,1.054) 54(14.968,-5.118) 55(15.469,1.054) 56(15.469,-5.118) 57(15.969,1.054) 58(15.969,-5.118) 59(16.469,1.054) 60(16.469,-5.118) 61(21.961,1.054) 62(21.961,-5.118) 63(22.461,1.054) 64(22.461,-5.118) 65(22.962,1.054) 66(22.962,-5.118) 67(23.462,1.054) 68(23.462,-5.118) 69(23.962,1.054) 70(23.962,-5.118) 71(24.463,1.054) 72(24.463,-5.118) 73(24.963,1.054) 74(24.963,-5.118) 75(25.463,1.054) 76(25.463,-5.118) 77(25.964,1.054) 78(25.964,-5.118) 79(26.464,1.054) 80(26.464,-5.118) 81(26.965,1.054) 82(26.965,-5.118) 83(27.465,1.054) 84(27.465,-5.118) 85(27.965,1.054) 86(27.965,-5.118) 87(28.466,1.054) 88(28.466,-5.118) 89(28.966,1.054) 90(28.966,-5.118) 91(29.467,1.054) 92(29.467,-5.118) 93(29.967,1.054) 94(29.967,-5.118) 95(30.467,1.054) 96(30.467,-5.118) 97(30.968,1.054) 98(30.968,-5.118) 99(31.468,1.054) 100(31.468,-5.118) 101(31.968,1.054) 102(31.968,-5.118) 103(32.469,1.054) 104(32.469,-5.118) 105(32.969,1.054) 106(32.969,-5.118) 107(33.47,1.054) 108(33.47,-5.118) 109(33.97,1.054) 110(33.97,-5.118) 111(34.47,1.054) 112(34.47,-5.118) 113(34.971,1.054) 114(34.971,-5.118) 115(35.471,1.054) 116(35.471,-5.118) 117(35.971,1.054) 118(35.971,-5.118) 119(36.472,1.054) 120(36.472,-5.118) 121(41.963,1.054) 122(41.963,-5.118) 123(42.464,1.054) 124(42.464,-5.118) 125(42.964,1.054) 126(42.964,-5.118) 127(43.464,1.054) 128(43.464,-5.118) 129(43.965,1.054) 130(43.965,-5.118) 131(44.465,1.054) 132(44.465,-5.118) 133(44.966,1.054) 134(44.966,-5.118) 135(45.466,1.054) 136(45.466,-5.118) 137(45.966,1.054) 138(45.966,-5.118) 139(46.467,1.054) 140(46.467,-5.118) 141(46.967,1.054) 142(46.967,-5.118) 143(47.468,1.054) 144(47.468,-5.118) 145(47.968,1.054) 146(47.968,-5.118) 147(48.468,1.054) 148(48.468,-5.118) 149(48.969,1.054) 150(48.969,-5.118) 151(49.469,1.054) 152(49.469,-5.118) 153(49.969,1.054) 154(49.969,-5.118) 155(50.47,1.054) 156(50.47,-5.118) 157(50.97,1.054) 158(50.97,-5.118) 159(51.471,1.054) 160(51.471,-5.118) 161(51.971,1.054) 162(51.971,-5.118) 163(52.471,1.054) 164(52.471,-5.118) 165(52.972,1.054) 166(52.972,-5.118) 167(53.472,1.054) 168(53.472,-5.118) 169(53.972,1.054) 170(53.972,-5.118) 171(54.473,1.054) 172(54.473,-5.118) 173(54.973,1.054) 174(54.973,-5.118) 175(55.474,1.054) 176(55.474,-5.118) 177(55.974,1.054) 178(55.974,-5.118) 179(56.474,1.054) 180(56.474,-5.118)
  rect 2.54x0.635 smd: 181(0.765,-2.032) 184(17.656,-2.032) 185(20.767,-2.032) 188(37.658,-2.032) 189(40.77,-2.032) 192(57.661,-2.032)
  rect 4.699x0.635 smd: 182(6.035,-2.032) 183(12.385,-2.032) 186(26.038,-2.032) 187(32.388,-2.032) 190(46.04,-2.032) 191(52.39,-2.032)
DBV5
  rect 1.4x0.5 smd: 1(-1.1,0.95) 2(-1.1,0) 3(-1.1,-0.95) 4(1.1,-0.95) 5(1.1,0.95)
FILTER_8_SM_150X150
  rect 1.524x0.635 smd: 1(-1.905,1.27) 2(-1.905,0) 3(-1.905,-1.27) 5(1.905,-1.27) 6(1.905,0) 7(1.905,1.27)
  rect 0.635x2.388 smd: 4(0,-1.27)
  rect 0.635x1.524 smd: 8(0,1.905)
HDR_THVT_1X2_100_M
  rect 1.473x1.473 hole 0.965: 1(0,0)
  round 1.473 hole 0.965: 2(0,-2.54)
HDR_THVT_1X3_100_M
  rect 1.473x1.473 hole 0.965: 1(0,0)
  round 1.473 hole 0.965: 2(0,-2.54) 3(0,-5.08)
HDR_THVT_2X5_100_M
  rect 1.473x1.473 hole 0.965: 1(0,0)
  round 1.473 hole 0.965: 2(2.54,0) 3(0,-2.54) 4(2.54,-2.54) 5(0,-5.08) 6(2.54,-5.08) 7(0,-7.62) 8(2.54,-7.62) 9(0,-10.16) 10(2.54,-10.16)
IND_0402
  rect 0.406x0.66 smd: 1(-0.432,0) 2(0.432,0)
JUMPER2
  round 1.524 hole 0.914: 1(0,0) 2(2.54,0)
LED_0805
  rect 1.422x1.524 smd: 1(-1.143,0) 2(1.143,0)
LPS3015
  custom 0.286x0.286 smd: 1(-1.143,0) 2(1.143,0)
MOSFET_8_2MMX2MM_0P65
  rect 0.4x0.47 smd: 1(-0.653,-0.91) 2(-0.003,-0.91) 3(0.647,-0.91) 4(0.647,0.91) 5(-0.003,0.91) 6(-0.653,0.91)
  rect 0.406x0.762 smd: 7(0.647,0.109)
  rect 1.016x1.016 smd: 8(-0.308,0)
OSC_4_SM_460X386
  rect 1.524x2.032 smd: 1(-3.81,-4.2) 4(3.81,-4.2) 5(3.81,4.2) 8(-3.81,4.2)
QFN64
  custom 0.076x0.076 smd: 1(-4.5,3.75) 2(-4.5,3.25) 3(-4.5,2.75) 4(-4.5,2.25) 5(-4.5,1.75) 6(-4.5,1.25) 7(-4.5,0.75) 8(-4.5,0.25) 9(-4.5,-0.25) 10(-4.5,-0.75) 11(-4.5,-1.25) 12(-4.5,-1.75) 13(-4.5,-2.25) 14(-4.5,-2.75) 15(-4.5,-3.25) 16(-4.5,-3.75) 17(-3.75,-4.5) 18(-3.25,-4.5) 19(-2.75,-4.5) 20(-2.25,-4.5) 21(-1.75,-4.5) 22(-1.25,-4.5) 23(-0.75,-4.5) 24(-0.25,-4.5) 25(0.25,-4.5) 26(0.75,-4.5) 27(1.25,-4.5) 28(1.75,-4.5) 29(2.25,-4.5) 30(2.75,-4.5) 31(3.25,-4.5) 32(3.75,-4.5) 33(4.5,-3.75) 34(4.5,-3.25) 35(4.5,-2.75) 36(4.5,-2.25) 37(4.5,-1.75) 38(4.5,-1.25) 39(4.5,-0.75) 40(4.5,-0.25) 41(4.5,0.25) 42(4.5,0.75) 43(4.5,1.25) 44(4.5,1.75) 45(4.5,2.25) 46(4.5,2.75) 47(4.5,3.25) 48(4.5,3.75) 49(3.75,4.5) 50(3.25,4.5) 51(2.75,4.5) 52(2.25,4.5) 53(1.75,4.5) 54(1.25,4.5) 55(0.75,4.5) 56(0.25,4.5) 57(-0.25,4.5) 58(-0.75,4.5) 59(-1.25,4.5) 60(-1.75,4.5) 61(-2.25,4.5) 62(-2.75,4.5) 63(-3.25,4.5) 64(-3.75,4.5)
  rect 6.096x6.096 smd: 65(0,0)
QFN_24_163X163_0P50MM_PWRPAD
  oval 0.762x0.305 smd: 1(-2.012,1.25) 2(-2.012,0.75) 3(-2.012,0.25) 4(-2.012,-0.25) 5(-2.012,-0.75) 6(-2.012,-1.25) 13(2.012,-1.25) 14(2.012,-0.75) 15(2.012,-0.25) 16(2.012,0.25) 17(2.012,0.75) 18(2.012,1.25)
  oval 0.305x0.762 smd: 7(-1.25,-2.012) 8(-0.75,-2.012) 9(-0.25,-2.012) 10(0.25,-2.012) 11(0.75,-2.012) 12(1.25,-2.012) 19(1.25,2.012) 20(0.75,2.012) 21(0.25,2.012) 22(-0.25,2.012) 23(-0.75,2.012) 24(-1.25,2.012)
  rect 2.54x2.54 smd: 25(0,0)
SMA_SMEL_218X247_096
  rect 0.381x1.27 smd: 1(0,-0.635)
  round 1.346 hole 1.143: 2(-1.219,-1.753) 3(1.219,-1.753) 4(-1.219,-3.962) 5(1.219,-3.962)
SMA_SMEL_250X215
  rect 0.813x4.064 smd: 1(0,-2.032)
  rect 1.524x4.064 smd: 2(-2.794,-2.032) 3(2.794,-2.032) 4(-2.794,-2.032) 5(2.794,-2.032)
SMA_THVT_312X312
  round 2.337 hole 1.575: 1(0,0)
  round 2.464 hole 1.702: 2(-2.54,2.54) 3(2.54,2.54) 4(2.54,-2.54) 5(-2.54,-2.54)
SMD_LED_0805
  rect 1.219x1.219 smd: 1(-1.016,0) 2(1.016,0)
SMD_XTAL_7X5MM_D75ASERIES
  rect 1.295x0.762 smd: (-2.083,-1.27) (-2.083,0) (-2.083,1.27) (2.083,-1.27) (2.083,0) 8(2.083,1.27)
  rect 0.94x1.295 smd: (-1.27,3.099) 4(-1.27,-3.099) 5(1.27,-3.099) 9(1.27,3.099)
SON_DRV_6
  rect 0.66x0.254 smd: 1(-1.152,0.65) 2(-1.152,0) 3(-1.152,-0.65) 4(1.152,-0.65) 5(1.152,0) 6(1.152,0.65)
  rect 1.016x1.626 smd: 7(0,0)
SON_DRY_6
  rect 0.254x0.356 smd: 1(-0.5,-0.33) 2(0,-0.33) 3(0.5,-0.33) 4(0.5,0.21) 5(0,0.21) 6(-0.5,0.21)
SOT_223_6_TG
  rect 0.762x2.388 smd: 1(-3.175,-3.378) 2(-1.905,-3.378) 3(-0.635,-3.378) 4(0.635,-3.378) 5(1.905,-3.378)
  rect 3.81x2.286 smd: 6(-0.635,2.997)
SSOP_28_413X221_26
  rect 2.032x0.457 smd: 1(-3.425,4.225) 2(-3.425,3.575) 3(-3.425,2.925) 4(-3.425,2.275) 5(-3.425,1.625) 6(-3.425,0.975) 7(-3.425,0.325) 8(-3.425,-0.325) 9(-3.425,-0.975) 10(-3.425,-1.625) 11(-3.425,-2.275) 12(-3.425,-2.925) 13(-3.425,-3.575) 14(-3.425,-4.225) 15(3.425,-4.225) 16(3.425,-3.575) 17(3.425,-2.925) 18(3.425,-2.275) 19(3.425,-1.625) 20(3.425,-0.975) 21(3.425,-0.325) 22(3.425,0.325) 23(3.425,0.975) 24(3.425,1.625) 25(3.425,2.275) 26(3.425,2.925) 27(3.425,3.575) 28(3.425,4.225)
SW_RESET_PTS635
  round 2.032 hole 1.397: 1(-3.251,0) 2(3.251,0)
TANT_A
  rect 1.524x1.397 smd: 1(-1.283,0) 2(1.283,0)
TANT_B
  rect 1.6x2.413 smd: 1(-1.867,0) 2(1.867,0)
TESTPOINT
  round 1.524 hole 1.016: 1(0,0)
TESTPOINT_62DIA
  round 2.337 hole 1.575: 1(0,0)
TFMR_6_RF_DUAL_FOOTPRINT
  rect 1.27x1.778 smd: 1(-2.54,-2.794) 2(0,-2.794) 3(2.54,-2.794) 4(2.54,2.794) 5(0,2.794) 6(-2.54,2.794)
TO_263_6
  rect 1.016x5.08 smd: 1(-3.404,-7.176) 2(-1.702,-7.176) 3(0,-7.176) 4(1.702,-7.176) 5(3.404,-7.176)
  rect 10.16x9.144 smd: 6(0,1.41)
unnamed#2
  round 2.286 hole 3.175 unplated: (0,0)
unnamed#3
  round 1.016 smd: 1(0,0)
VCXO_6_CUSTOM2
  rect 5.029x1.422 smd: 1(-4,2.54) 2(-4,0) 3(-4,-2.54) 4(4,-2.54) 5(4,0) 6(4,2.54)

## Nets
3.3V_CDC_CP: C50.1 C53.1 C61.2 C65.2 FB13.1 R73.2 R80.2 R87.2 U2.64(VCC_CP) VCXO1.6(VCC)
5V: C128.1 C187.1 C414.1 JP10.1 JP14.1 JP19.1 R131.2 U14.4(OUT)
+1.8V_CLK: C2.1 C3.1 C4.1 FB11.1 U1.10(DVDD18_CLK)
+1.8VA_ADC: C23.1 C24.1 C25.1 C26.1 C27.1 C28.1 C29.1 C30.1 C31.1 C32.1 C35.1 FB17.1 U1.1(AVDD18_ADC#1) U1.4(AVDD18_ADC#4) U1.7(AVDD18_ADC#7) U1.62(AVDD18_ADC#62) U1.64(AVDD18_ADC#64)
+1.8VD: C5.1 C6.1 C7.1 C8.1 C9.1 C10.1 C11.1 C12.1 C13.1 C19.1 C20.1 C139.1 C148.1 C149.1 C150.1 FB11.3 FB17.3 JP1.3(PIN3) R145.2 SW1.2 U1.19(DVDD18_DAC) U1.25(FUSE_VDD) U1.32(DVDD18#32) U1.41(DVDD18#41) U1.49(DVDD18#49)
+3.3V_CLK: C59.1 C62.1 C63.1 C64.1 C66.1 C67.1 C68.1 C69.1 C76.1 C77.1 C78.1 C80.1 C82.1 C84.1 C86.1 C88.1 C144.1 C146.1 C179.1 FB13.2 JP7.1(PIN1) JP17.2 JP18.2 R85.2 R98.2 R99.2 R100.2 R101.2 R105.2 R106.2 R107.2 R110.2 R148.1 R149.1 R166.1 U2.4(VCC_PLL#4) U2.5(VCC#5) U2.8(VCC#8) U2.11(VCC#11) U2.14(VCC#14) U2.19(VCC#19) U2.22(VCC#22) U2.25(VCC#25) U2.28(VCC#28) U2.31(VCC#31) U2.34(VCC#34) U2.37(VCC#37) U2.40(VCC#40) U2.43(VCC#43) U2.48(AVCC#48) U2.49(AVCC#49) U2.51(AVCC#51) U2.54(AVCC#54) U2.57(VCC_PLL#57) U2.60(VCC_PLL#60) U2.63(VCC_PLL#63)
+3.3VA_DAC: C14.1 C15.1 C16.1 C17.1 C18.1 C21.1 C22.1 C33.1 C34.1 C131.1 C143.1 C145.1 C147.1 FB15.1 R12.1 R13.1 R48.2 R50.2 R53.1 R54.1 R143.2 U1.11(AVDD3_DAC#11) U1.14(AVDD3_DAC#14) U1.17(AVDD3_DAC#17) U1.22(AVDD3_AUX)
+5VA: FB4.1 FB5.1 JP10.2 R113.1 R118.1 R126.1 R132.1
+6.0VDC: C123.1 C124.1 C125.1 C186.1 FB7.1 JP11.1 JP20.1 R142.2 U14.1(EN) U14.2(IN)
GND: C1.2 C2.2 C3.2 C4.2 C5.2 C6.2 C7.2 C8.2 C9.2 C10.2 C11.2 C12.2 C13.2 C14.2 C15.2 C16.2 C17.2 C18.2 C19.2 C20.2 C21.2 C22.2 C23.2 C24.2 C25.2 C26.2 C27.2 C28.2 C29.2 C30.2 C31.2 C32.2 C33.2 C34.2 C35.2 C37.1 C39.1 C40.1 C43.1 C45.1 C46.1 C48.1 C49.1 C50.2 C52.1 C53.2 C56.2 C59.2 C60.1 C61.1 C62.2 C63.2 C64.2 C65.1 C66.2 C67.2 C68.2 C69.2 C72.1 C73.1 C75.2 C76.2 C77.2 C78.2 C79.2 C80.2 C81.2 C82.2 C84.2 C85.1 C86.2 C88.2 C89.2 C95.1 C96.1 C97.2 C98.2 C99.2 C100.2 C101.2 C102.2 C104.2 C105.2 C108.1 C109.1 C115.2 C116.2 C117.2 C118.2 C119.2 C120.2 C121.2 C122.2 C123.2 C124.2 C125.2 C128.2 C130.2 C131.2 C132.2 C133.2 C135.2 C136.2 C137.2 C138.2 C139.2 C140.2 C141.2 C142.2 C143.2 C144.2 C145.2 C146.2 C147.2 C148.2 C149.2 C150.2 C151.2 C178.2 C179.2 C180.2 C181.2 C182.2 C186.2 C187.2 D1.2(CATHODE) D2.2(CATHODE) FB9.2 FB11.2 FB12.2 FB15.2 FB17.2 FLT1.2(GND#2) FLT1.3(GND#3) FLT1.4(GND#4) FLT1.6(GND#6) FLT1.7(GND#7) FLT1.8(GND#8) J1.2(GND#2) J1.3(GND#3) J1.4(GND#4) J1.5(GND#5) J2.2(GND#2) J2.3(GND#3) J2.4(GND#4) J2.5(GND#5) J3.2(GND#2) J3.3(GND#3) J3.4(GND#4) J3.5(GND#5) J4.2(GND#2) J4.3(GND#3) J4.4(GND#4) J4.5(GND#5) J5.2(SHIELD1) J5.3(SHIELD2) J5.4(SHIELD3) J5.5(SHIELD4) J6.2(SHIELD1) J6.3(SHIELD2) J6.4(SHIELD3) J6.5(SHIELD4) J7.2(SHIELD1) J7.3(SHIELD2) J7.4(SHIELD3) J7.5(SHIELD4) J8.2(SHIELD1) J8.3(SHIELD2) J8.4(SHIELD3) J8.5(SHIELD4) J9.2(GND#2) J9.3(GND#3) J9.4(GND#4) J9.5(GND#5) J10.2(GND#2) J10.3(GND#3) J10.4(GND#4) J10.5(GND#5) J11.2(GND#2) J11.3(GND#3) J11.4(GND#4) J11.5(GND#5) J12.2(GND#2) J12.3(GND#3) J12.4(GND#4) J12.5(GND#5) J13.2(GND#2) J13.3(GND#3) J13.4(GND#4) J13.5(GND#5) J14.5 J14.6 J14.11 J14.12 J14.17 J14.18 J14.23 J14.24 J14.29 J14.30 J14.35 J14.36 J14.41 J14.42 J14.47 J14.48 J14.53 J14.54 J14.59 J14.60 J14.61 J14.62 J14.67 J14.68 J14.73 J14.74 J14.79 J14.80 J14.85 J14.86 J14.91 J14.92 J14.97 J14.98 J14.103 J14.104 J14.109 J14.110 J14.116 J14.121(GND#121) J14.122(GND#122) J14.123(GND#123) J14.124(GND#124) J14.125(GND#125) J14.126(GND#126) J14.127(GND#127) J14.128(GND#128) J15.181(GND#181) J15.182(GND#182) J15.183(GND#183) J15.184(GND#184) J15.185(GND#185) J15.186(GND#186) J15.187(GND#187) J15.188(GND#188) J15.189(GND#189) J15.190(GND#190) J15.191(GND#191) J15.192(GND#192) J16.5(GND) J16.6(GND1) J16.7(GND2) J16.8(GND3) J16.9(GND4) J17.2 J17.3 J18.2(GND#2) J18.3(GND#3) J18.4(GND#4) J18.5(GND#5) J19.2(GND#2) J19.3(GND#3) J19.4(GND#4) J19.5(GND#5) J20.1 J20.10 J21.2(SHIELD1) J21.3(SHIELD2) J21.4(SHIELD3) J21.5(SHIELD4) JP1.1(PIN1) JP2.2 JP3.2 JP4.3 JP5.3(PIN3) JP6.2 JP7.3(PIN3) JP8.2 JP15.2 JP16.2 L8.2 L9.2 R5.2 R14.1 R24.2 R26.1 R31.2 R37.2 R39.1 R45.2 R52.2 R63.2 R77.2 R83.2 R86.2 R89.2 R90.1 R96.2 R97.2 R102.1 R103.1 R104.1 R108.1 R116.2 R119.1 R122.2 R123.1 R124.2 R129.2 R135.2 R150.2 R151.2 R164.1 R167.1 SW2.2 T5.3(PRIMARY_DOT) T6.1(PRIMARY) T7.3(PRIMARY_DOT) TP2.1(TP) TP3.1(TP) TP12.1(TP) U1.65(PWRPAD) U2.2(GND_CP) U2.32(GND) U2.58(PRI_REF-) U2.61(SEC_REF-) U2.65(THERMAL_PAD) U3.2(GND#2) U3.5(GND#5) U3.8(GND#8) U3.11(GND#11) U3.12(GND#12) U3.14(GND#14) U3.17(GND#17) U3.19(GND#19) U3.20(GND#20) U3.23(GND#23) U3.25(PWRPAD) U4.7(GND#7) U4.18(GND#18) U4.21(GND#21) U4.25(AGND) U4.26(TEST) U6.2(MODE) U6.6(GND) U6.7(THERMPAD) U7.3(GND#3) U7.6(GND#6) U8.1(MODE) U8.4(GND) U9.3(GND#3) U9.6(GND#6) U14.3(GND#3) U14.6(GND#6) U16.4(GND) U17.4(GND) U18.2(GND) VCXO1.3(GND)
ADC_A_INN: R41.2 R44.2 U1.5(INN_A_ADC)
ADC_A_INP: R34.2 R35.1 U1.6(INP_A_ADC)
ADC_B_INN: R28.2 R32.2 U1.2(INN_B_ADC)
ADC_B_INP: R21.2 R23.1 U1.3(INP_B_ADC)
ADC_DCLKOUTN: J14.56 U1.50(ADC_DCLKOUTN)
ADC_DCLKOUTP: J14.58 U1.51(ADC_DCLKOUTP)
ADC_FCLKOUTN: J14.64 U1.46(ADC_FCLKOUTN)
ADC_FCLKOUTP: J14.66 U1.47(ADC_FCLKOUTP)
ADCA_DATA_0N: J14.44 U1.54(ADCA_DATA_0N)
ADCA_DATA_0P: J14.46 U1.55(ADCA_DATA_0P)
ADCA_DATA_1N: J14.50 U1.52(ADCA_DATA_1N)
ADCA_DATA_1P: J14.52 U1.53(ADCA_DATA_1P)
ADCB_DATA_0N: J14.70 U1.44(ADCB_DATA_0N)
ADCB_DATA_0P: J14.72 U1.45(ADCB_DATA_0P)
ADCB_DATA_1N: J14.76 U1.42(ADCB_DATA_1N)
ADCB_DATA_1P: J14.78 U1.43(ADCB_DATA_1P)
ADCDATA6: J14.84 U1.48(NC/ADCDATA6)
AUX_SEL: JP7.2(PIN2) U2.18(AUX_SEL)
AUXADC-A: JP15.1 R18.2
AUXADC-B: JP16.1 R19.2
AUXADC_A: R18.1 U1.23(AUXADC_A)
AUXADC_B: R19.1 U1.24(AUXADC_B)
AUXDAC-A: JP2.1 R16.2
AUXDAC-B: JP3.1 R17.2
AUXDAC_A: R16.1 R52.1 U1.20(AUXDAC_A)
AUXDAC_B: R17.1 R63.1 U1.21(AUXDAC_B)
CDC_PWRDWN: C89.1 R110.1 R111.2 U2.17(/POWER_DOWN)
CDC_REF: C57.1 R75.1
CDC_REFIN: C57.2 R85.1 R90.2 U2.59(PRI_REF+)
CDC_RESET: C75.1 R106.1 R109.1 U2.33(/RESET OR /HOLD)
CDC_SEC_REF: C177.2 R166.2 R167.2 U2.62(SEC_REF+)
CLKIN: J18.1(CENTER) R112.2
CLKINN: C55.2 R88.2 U1.8(CLKINN)
CLKINP: C51.2 R88.1 U1.9(CLKINP)
CLOCK_IN: R74.2 R77.1 R112.1
CLOCKIN: J9.1(CENTER) R75.2
CP_OUT: C49.2 R70.2 R71.2 U2.3(CP_OUT)
DAC_DCLK_INN: R62.2 R93.1 R95.2 U1.34(DAC_DCLK_INN)
DAC_DCLK_INP: R62.1 R64.1 R94.2 U1.33(DAC_DCLK_INP)
DAC_FCLK_INN: J15.93 R65.2 U1.31(DAC_FCLK_INN)
DAC_FCLK_INP: J15.91 R65.1 U1.30(DAC_FCLK_INP)
DACA_DATA_0N: J15.75 R66.2 U1.29(DACA_DATA_0N)
DACA_DATA_0P: J15.73 R66.1 U1.28(DACA_DATA_0P)
DACA_DATA_1N: J15.69 R67.2 U1.27(DACA_DATA_1N)
DACA_DATA_1P: J15.67 R67.1 U1.26(DACA_DATA_1P)
DACB_DATA_0N: J15.81 R60.2 U1.36(DACB_DATA_0N)
DACB_DATA_0P: J15.79 R60.1 U1.35(DACB_DATA_0P)
DACB_DATA_1N: J15.87 R55.2 U1.38(DACB_DATA_1N)
DACB_DATA_1P: J15.85 R55.1 U1.37(DACB_DATA_1P)
DACCLK_IN: J21.1(CENTER) T6.3(PRIMARY_DOT)
FPGA_CLKN: J15.118 R149.2 R151.1 U2.12(U2N)
FPGA_CLKP: J15.116 R148.2 R150.1 U2.13(U2P)
FPGA_SCLK: J14.115 R3.2
FPGA_SDATA: J14.117 R8.2
FPGA_SDO: J14.113 R51.2
FPGA_SEN: J14.119 R10.2
IN1: C95.2 R125.1 R155.2 U3.22(IN)
INA+: J3.1(CENTER) R36.1
INA-: J4.1(CENTER) R42.2
INB+: J1.1(CENTER) R22.1
INB-: J2.1(CENTER) R29.2
IOUT-N-A: J6.1(CENTER) R57.2
IOUT-N-B: J8.1(CENTER) R69.2
IOUT-P-A: J5.1(CENTER) R49.2 T5.1(PRIMARY)
IOUT-P-B: J7.1(CENTER) R61.2 T7.1(PRIMARY)
IOUTN-A: R13.2 R56.1 R57.1 T5.4(SECONDARY_DOT)
IOUTN-B: R54.2 R68.1 R69.1 T7.4(SECONDARY_DOT)
IOUTN_A: R56.2 R133.2 U1.13(IOUTN_A_DAC)
IOUTN_B: R68.2 R114.2 U1.16(IOUTN_B_DAC)
IOUTP-A: R12.2 R46.1 R47.1 T5.6(SECONDARY)
IOUTP-B: R53.2 R58.1 R59.1 T7.6(SECONDARY)
IOUTP_A: R46.2 R127.2 U1.12(IOUTP_A_DAC)
IOUTP_B: R58.2 R120.2 U1.15(IOUTP_B_DAC)
IP1: C96.2 R117.1 R155.1 U3.21(IP)
MODE_SEL: JP5.2(PIN2) U2.16(MODE_SEL)
OUT: C58.1 VCXO1.4(OUT)
OUTB: C54.1 VCXO1.5(OUTB)
PDN: JP1.2(PIN2) U1.56(PDN)
PLL_LOCK: R91.2 U2.50(PLL_LOCK)
PLLLOCK: R91.1 R92.2
PWRDWN: JP8.1 R111.1
QN1: C108.2 R140.1 R154.2 U3.9(QN)
QP1: C109.2 R130.1 R154.1 U3.10(QP)
REF_SEL: R101.1 U2.47(REF_SEL)
RF_LO_IN: C103.1 J12.1(CENTER)
RFOUT: C106.2 J13.1(CENTER)
RST: JP6.1 R109.2 SW2.1
SCLK: R1.1 R3.1 U1.59(SCLK)
SDATA: R6.1 R8.1 U1.58(SDATA)
SDO: R11.1 R51.1 U1.60(SDOUT)
SEN: R9.1 R10.1 U1.57(SEN)
SPI_CLK: J20.4 R100.1 R104.2 R159.1 U2.46(SPI_CLK)
SPI_LE: J20.2 R99.1 R103.2 R136.1 U2.45(SPI_LE)
SPI_MISO: J20.8 R158.1 U2.15(SPI_MISO)
SPI_MOSI: J20.6 R98.1 R102.2 R160.1 U2.44(SPI_MOSI)
SYNCINN: J15.175 U1.40(SYNCINN)
SYNCINP: J15.173 U1.39(SYNCINP)
TCXO_VCC: C178.1 C181.1 C182.1 FB25.1 R165.2 U16.9(VDD) U17.8(VDD)
USB_SCLK: R1.2 R137.1
USB_SDATA: R6.2 R138.1
USB_SDO: R11.2 R141.1
USB_SEN: R9.2 R139.1
V_CTRL: C48.2 R70.1 TP4.1(TP) VCXO1.1(V_CTRL)
VBB: C85.2 R84.1 U2.56(VBB)
VCM: C37.2 C43.2 R7.1 R25.2 R27.1 R38.2 R40.1 TP1.1(TP)
VCXO_IN: C58.2 R87.1 R89.1 U2.53(VCXO_IN+)
VCXO_INB: C54.2 R80.1 R83.1 R84.2 U2.52(VCXO_IN-)
Y0: C70.1 R76.2 R144.2
Y0P: C71.2 R72.2 U2.7(U0P)
Y0P_FLTR: C71.1 C72.2 FLT1.1(IN) L9.1
Y1N: R81.2 R96.1 U2.9(U1N)
Y1P: R79.2 R97.1 U2.10(U1P)
N27753747: C106.1 U3.16(RFOUT)
N27753749: C101.1 C102.1 C104.1 C105.1 FB5.2 U3.18(VCCI)
N27753751: C97.1 C98.1 C99.1 C100.1 FB4.2 U3.24(VCC2)
N27753768: C107.2 R124.1
N27753778: C107.1 U3.4(LON)
N27753917: C103.2 U3.3(LOP)
N27836198: C121.1 C122.1 F3.2 FB7.2 Q1.4(S4) Q1.7(S7)
N27836250: F3.1 J17.1 Q1.1(D1) Q1.2(D2) Q1.5(D5) Q1.6(D6) Q1.8(D8) TP11.1(TP) U18.5(VIN)
N27836254: D2.1(ANODE) R142.1
N28104733: C132.1 C133.1 JP12.1(PIN1) L18.2 U6.3(FB)
N28104810: L18.1 U6.1(SW)
N28106468: C130.1 JP11.2 U6.4(EN) U6.5(IN)
N28122875: C135.1 U7.5(NR/FB)
N28122877: C136.1 JP12.3(PIN3) U7.4(OUT)
N28122879: C151.1 JP19.2 U7.1(EN) U7.2(IN)
N28166986: C90.1 R113.2 R114.1 R115.1
N28167010: C92.1 L10.1 R117.2
N28167012: C90.2 C91.1 L10.2 R115.2 R116.1
N28167020: C92.2 L12.1 R125.2
N28167104: C94.1 R118.2 R120.1 R121.1
N28167112: C91.2 C94.2 L12.2 R121.2 R122.1
N28168729: C111.2 C114.2 L16.2 R134.2 R135.1
N28168733: C114.1 R132.2 R133.1 R134.1
N28168739: C112.1 L14.1 R130.2
N28168741: C112.2 L16.1 R140.2
N28287802: C110.2 C111.1 L14.2 R128.2 R129.1
N28296464: C110.1 R126.2 R127.1 R128.1
N29051346: R123.2 U3.1(NC1)
N29488937: R81.1 R86.1 T9.1(PRIMARY)
N29488984: R74.1 R76.1 R79.1 T9.3(PRIMARY_DOT)
N29489205: C74.2 R105.1 R108.2 U2.35(U7N)
N29489357: D1.1(ANODE) R92.1
N29489396: C56.1 R78.2 R82.1 T9.2(PRIMARY_CT) T9.5(SECONDARY_CT)
N29489542: C55.1 R82.2 R161.2 T9.6(SECONDARY)
N29489733: JP4.1 R73.1
N29489951: JP5.1(PIN1) R107.1
N29490085: C70.2 C73.2 FLT1.5(OUT) L8.1
N29490446: C51.1 R78.1 T9.4(SECONDARY_DOT)
N29490682: JP4.2 VCXO1.2(EN)
N29639772: R15.2 U1.18(BIASJ)
N29650049: C1.1 R7.2 U1.63(VCM)
N29655636: R2.2 R5.1 U1.61(RESET)
N29813891: R59.2 R61.1
N29813928: C81.1 R50.1 T7.5(SECONDARY_CT)
N29814161: R47.2 R49.1
N29814197: C79.1 R48.1 T5.5(SECONDARY_CT)
N29978719: R139.2 U4.11(D3)
N29978744: C116.1 FB6.2 J16.1(VBUS)
N29978873: C119.1 J16.2(D-) U4.16(USBDM)
N29978893: C115.1 C117.1 FB6.1 U4.20(VCC)
N29978897: R136.2 U4.1(D0)
N29978919: C120.1 U4.4(VCCIO) U4.17(3V3OUT)
N29978933: C118.1 J16.3(D+) U4.15(USBDP)
N29979080: R141.2 U4.6(D7)
N29979098: R138.2 U4.3(D2)
N29979142: R137.2 U4.5(D1)
N29981843: C36.1 R20.1
N29981855: C41.1 R30.1
N29981879: C36.2 R21.1 R25.1
N29981949: C39.2 T1.2(PRIMARY_CT) T1.5(SECONDARY_CT)
N29981953: C40.2 T2.2(PRIMARY_CT) T2.5(SECONDARY_CT)
N29982125: R24.1 T1.4(SECONDARY_DOT) T2.6(SECONDARY)
N29982131: R26.2 T1.6(SECONDARY) T2.4(SECONDARY_DOT)
N29982143: R20.2 T2.1(PRIMARY)
N29982145: R30.2 T2.3(PRIMARY_DOT)
N29982157: C41.2 R27.2 R32.1
N29982173: R29.1 R31.1 T1.1(PRIMARY)
N29999539: C42.1 R33.1
N29999545: C47.1 R43.1
N29999563: C42.2 R34.1 R38.1
N29999622: C45.2 T3.2(PRIMARY_CT) T3.5(SECONDARY_CT)
N29999634: C46.2 T4.2(PRIMARY_CT) T4.5(SECONDARY_CT)
N29999775: R37.1 T3.4(SECONDARY_DOT) T4.6(SECONDARY)
N29999779: R39.2 T3.6(SECONDARY) T4.4(SECONDARY_DOT)
N29999791: R33.2 T4.1(PRIMARY)
N29999793: R43.2 T4.3(PRIMARY_DOT)
N29999803: C47.2 R40.2 R44.1
N29999817: R42.1 R45.1 T3.1(PRIMARY)
N30111387: L19.1 U8.2(SW)
N30111389: C137.1 JP20.2 U8.3(IN) U8.5(EN)
N30111452: C138.1 JP13.1(PIN1) L19.2 U8.6(FB)
N30111497: FB12.1 JP13.2(PIN2)
N30111569: C140.1 JP14.2 U9.1(EN) U9.2(IN)
N30111571: C141.1 U9.5(NR/FB)
N30111598: C142.1 JP13.3(PIN3) U9.4(OUT)
N30152047: C38.2 L1.2 R28.1
N30152584: C38.1 L1.1 R23.2
N30155281: C44.1 L2.1 R35.2
N30155822: C44.2 L2.2 R41.1
N30525626: R22.2 T1.3(PRIMARY_DOT)
N30527255: R36.2 T3.3(PRIMARY_DOT)
N30929266: R72.1 R144.1
N31014668: R164.2 R165.1 TP14.1(TP) U16.8(EN) U17.1(REF)
N31014687: C177.1 R157.1 U17.5(OUT)
N31014712: C180.1 FB25.2 JP17.1
N31036180: R158.2 U4.2(D4)
N31036604: R159.2 U4.9(D5)
N31037032: R160.2 U4.10(D6)
N31071827: FB9.3 R143.1
N31076049: FB9.1 JP12.2(PIN2)
N31079418: FB12.3 R145.1
N31166599: J19.1(CENTER) R161.1
N31236900: C414.2 R119.2 R131.1 U14.5(NR/FB)
N31255553: FB15.3 JP18.1
N31355701: C83.1 U2.42(U9P OR AUXINP)
N31356519: C83.2 J10.1(CENTER)
N31627077: C60.2 T6.2(PRIMARY_CT) T6.5(SECONDARY_CT)
N31630401: R94.1 T6.4(SECONDARY_DOT)
N31630404: R95.1 T6.6(SECONDARY)
N31634141: J15.117 R93.2
N31634154: J15.115 R64.2
N31649883: Q1.3(G3) U18.4(GATE)
N294889280: C74.1 J11.1(CENTER)
N294896140: C52.2 R71.1
N296597010: R2.1 SW1.1
N298553540: R14.2 R15.1
N310146821: R157.2 U16.5(OUT)

Pads without a net: J14 1 2 3 4 7 8 9 10 13 14 15 16 19 20 21 22 25 26 27 28 31 32 33 34 37 38 39 40 43 45 49 51 55 57 63 65 69 71 75 77 81 82 83 87 88 89 90 93 94 95 96 99 100 101 102 105 106 107 108 111 112 114 118 120; J15 1 2 3 4 5 6 7 8 9 10 11 12 13 14 15 16 17 18 19 20 21 22 23 24 25 26 27 28 29 30 31 32 33 34 35 36 37 38 39 40 41 42 43 44 45 46 47 48 49 50 51 52 53 54 55 56 57 58 59 60 61 62 63 64 65 66 68 70 71 72 74 76 77 78 80 82 83 84 86 88 89 90 92 94 95 96 97 98 99 100 101 102 103 104 105 106 107 108 109 110 111 112 113 114 119 120 121 122 123 124 125 126 127 128 129 130 131 132 133 134 135 136 137 138 139 140 141 142 143 144 145 146 147 148 149 150 151 152 153 154 155 156 157 158 159 160 161 162 163 164 165 166 167 168 169 170 171 172 174 176 177 178 179 180; J16 4; J20 3 5 7 9; NOREF#19 1; NOREF#20 1; NOREF#25 1; NOREF#26 1; NOREF#27 1; NOREF#28 1; T5 2; T7 2; U2 1 6 20 21 23 24 26 27 29 30 36 38 39 41 55; U3 6 7 13 15; U4 8 12 13 14 19 22 23 24 27 28; U18 1 3

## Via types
v1: diameter 0.508, hole 0.254, TOP to BOTTOM, 2344 vias
v2: diameter 0.61, hole 0.33, TOP to BOTTOM, 50 vias
v3: diameter 0.254, hole 0.152, TOP to BOTTOM, 10 vias

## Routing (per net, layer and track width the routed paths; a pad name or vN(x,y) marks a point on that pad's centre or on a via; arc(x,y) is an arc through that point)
3.3V_CDC_CP: length 13
  TOP w0.305: C65.2 80.94,67.6 C61.2 82.19,66.37 v1(83.69,66.37) 84.08,66.73 U2.64 ; C65.2 v1(80.64,66.78) ; C65.2 80.04,66.7 80.04,66.5 ; 80.04,66.5 v1(80.21,66.32) ; 80.04,66.5 FB13.1 79.63,66.06 v1(79.73,65.96)
  TOP w0.508: R87.2 v1(87.03,85.62) ; R73.2 v1(102.46,97.82) ; R80.2 v1(91.11,85.6) ; VCXO1.6 v1(92.94,90.81)
  BOTTOM w0.508: C53.1 v1(94.41,93.42) ; C50.1 v1(94.28,94.95)
